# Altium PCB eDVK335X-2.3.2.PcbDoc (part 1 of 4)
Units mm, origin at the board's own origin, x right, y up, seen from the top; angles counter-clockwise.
Board outline 100.04 x 80.07 mm, 4 copper layers (Top Layer, Layer 1, Layer 2, Bottom Layer), stack 0.569 mm thick; 245 components, 272 nets, 1313 pads, 662 vias.
Unrouted connection lines stored in the file: 1.
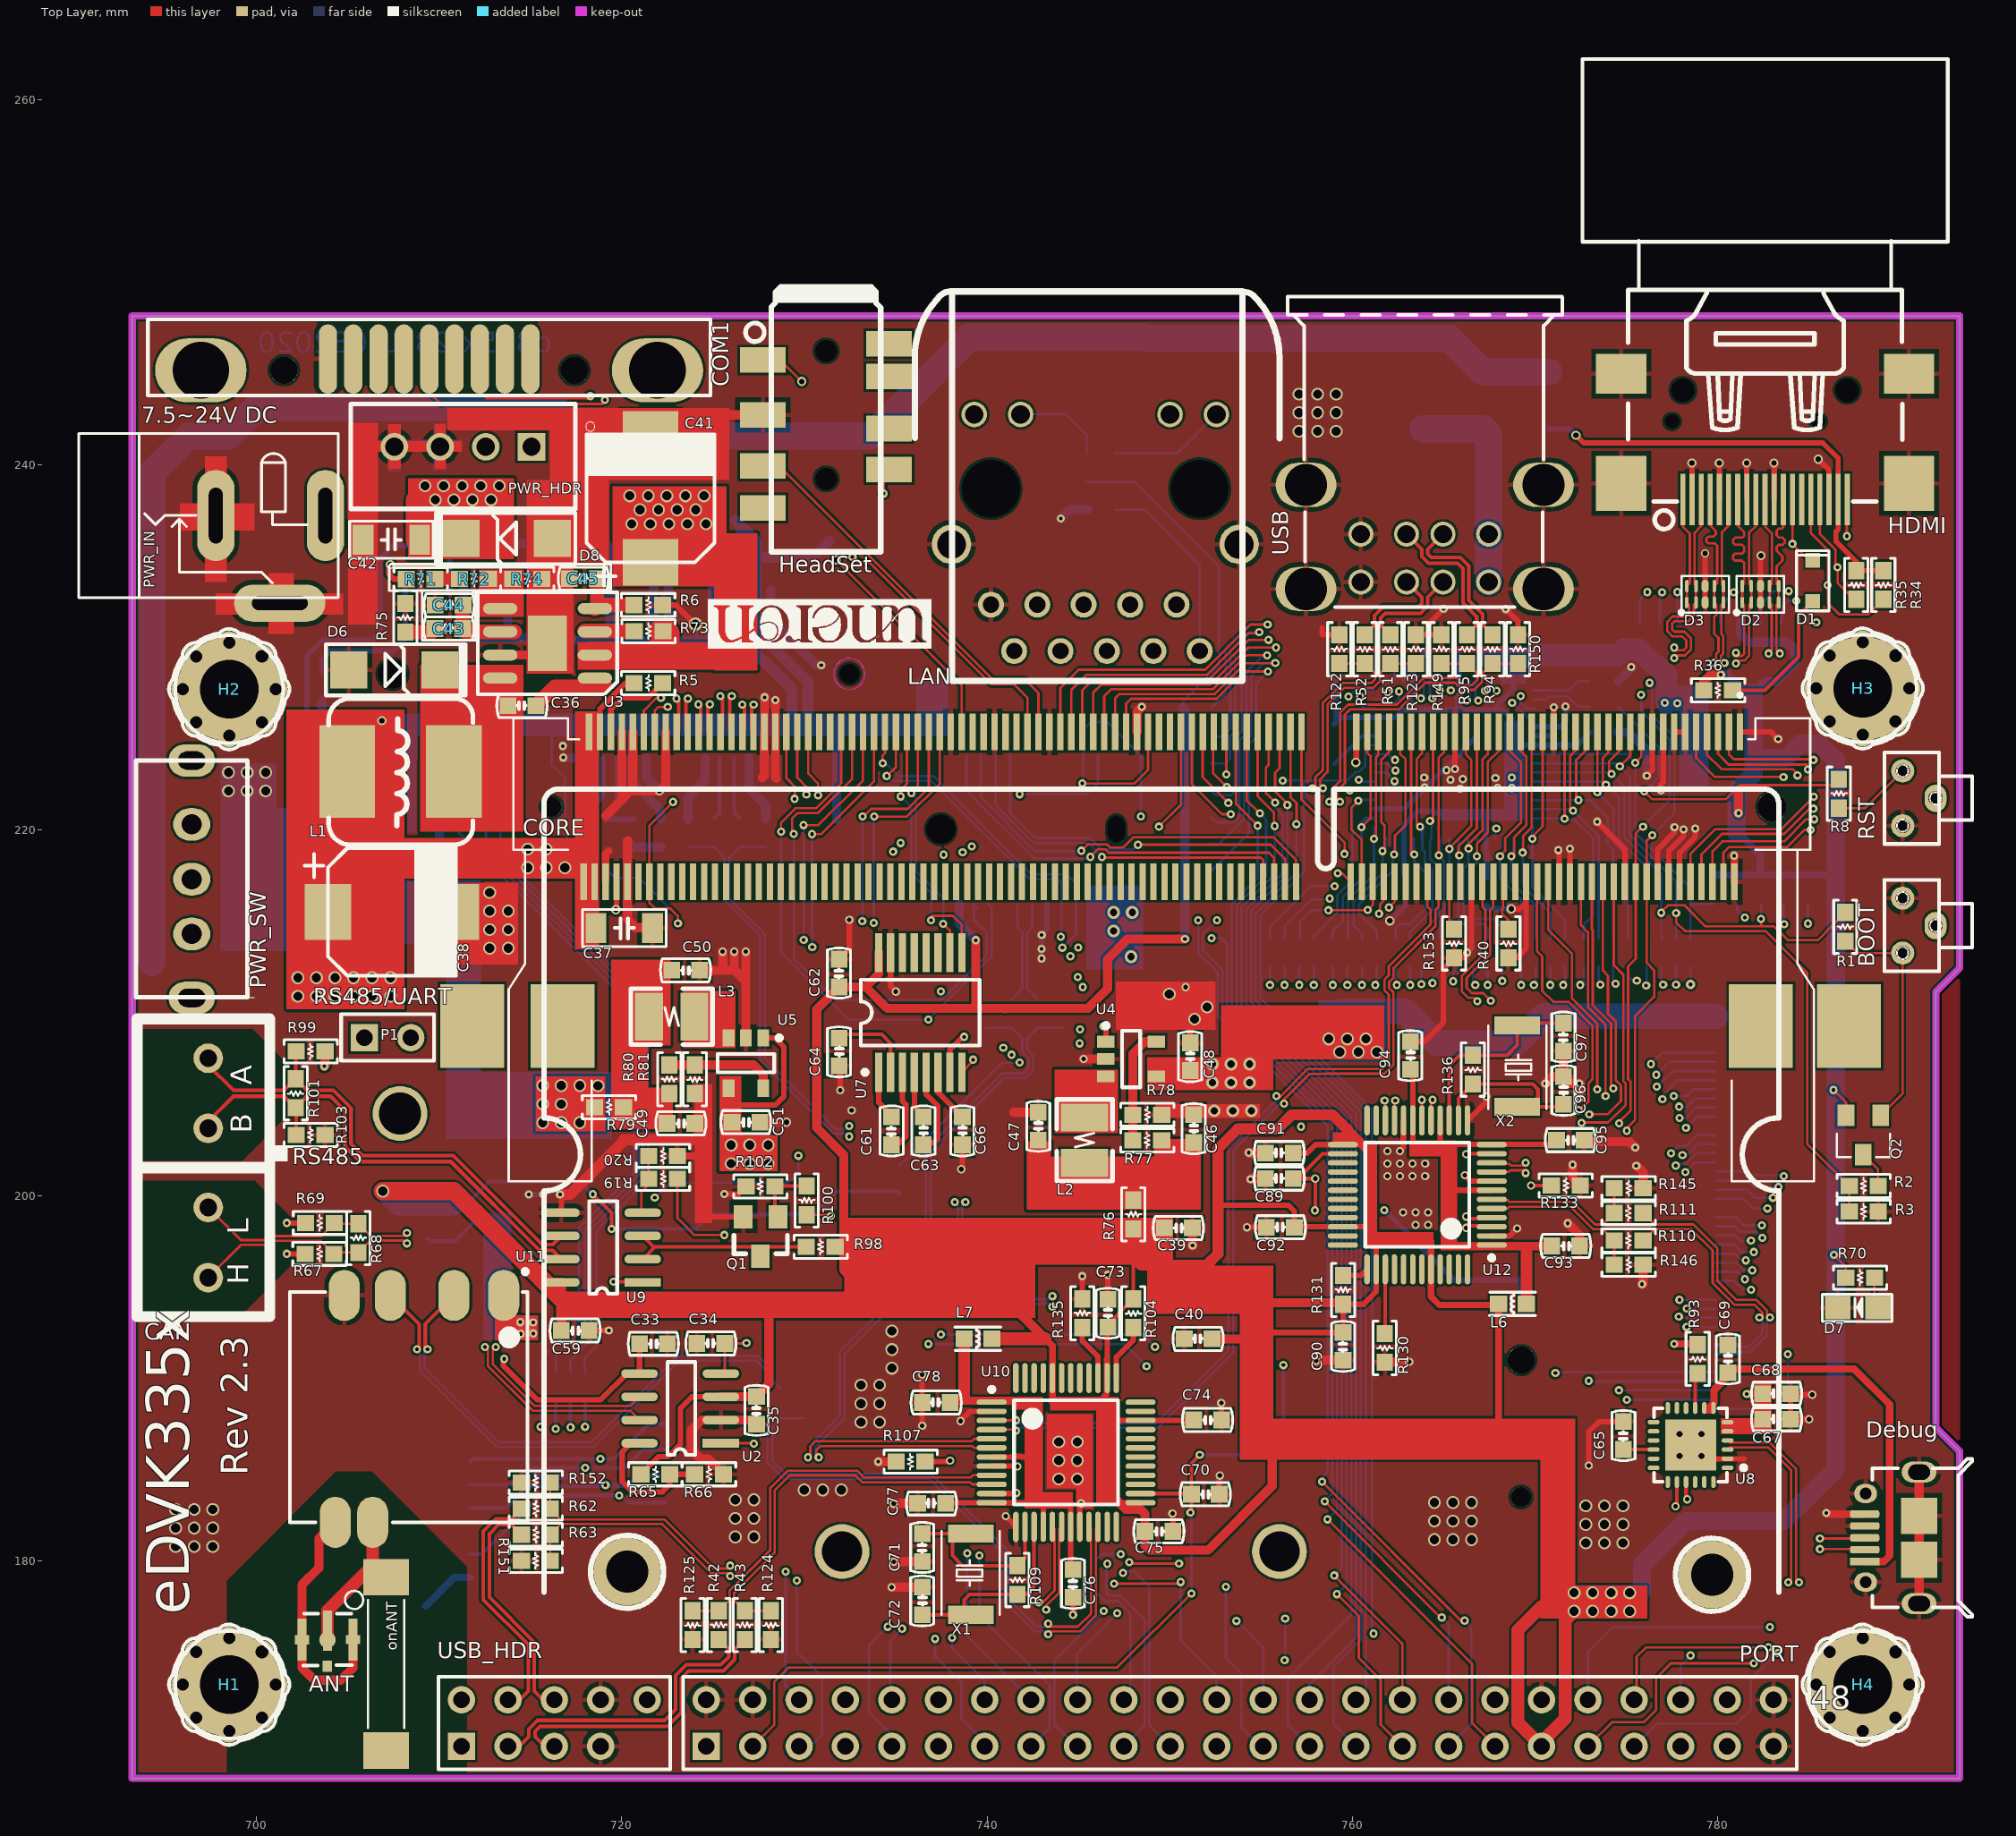
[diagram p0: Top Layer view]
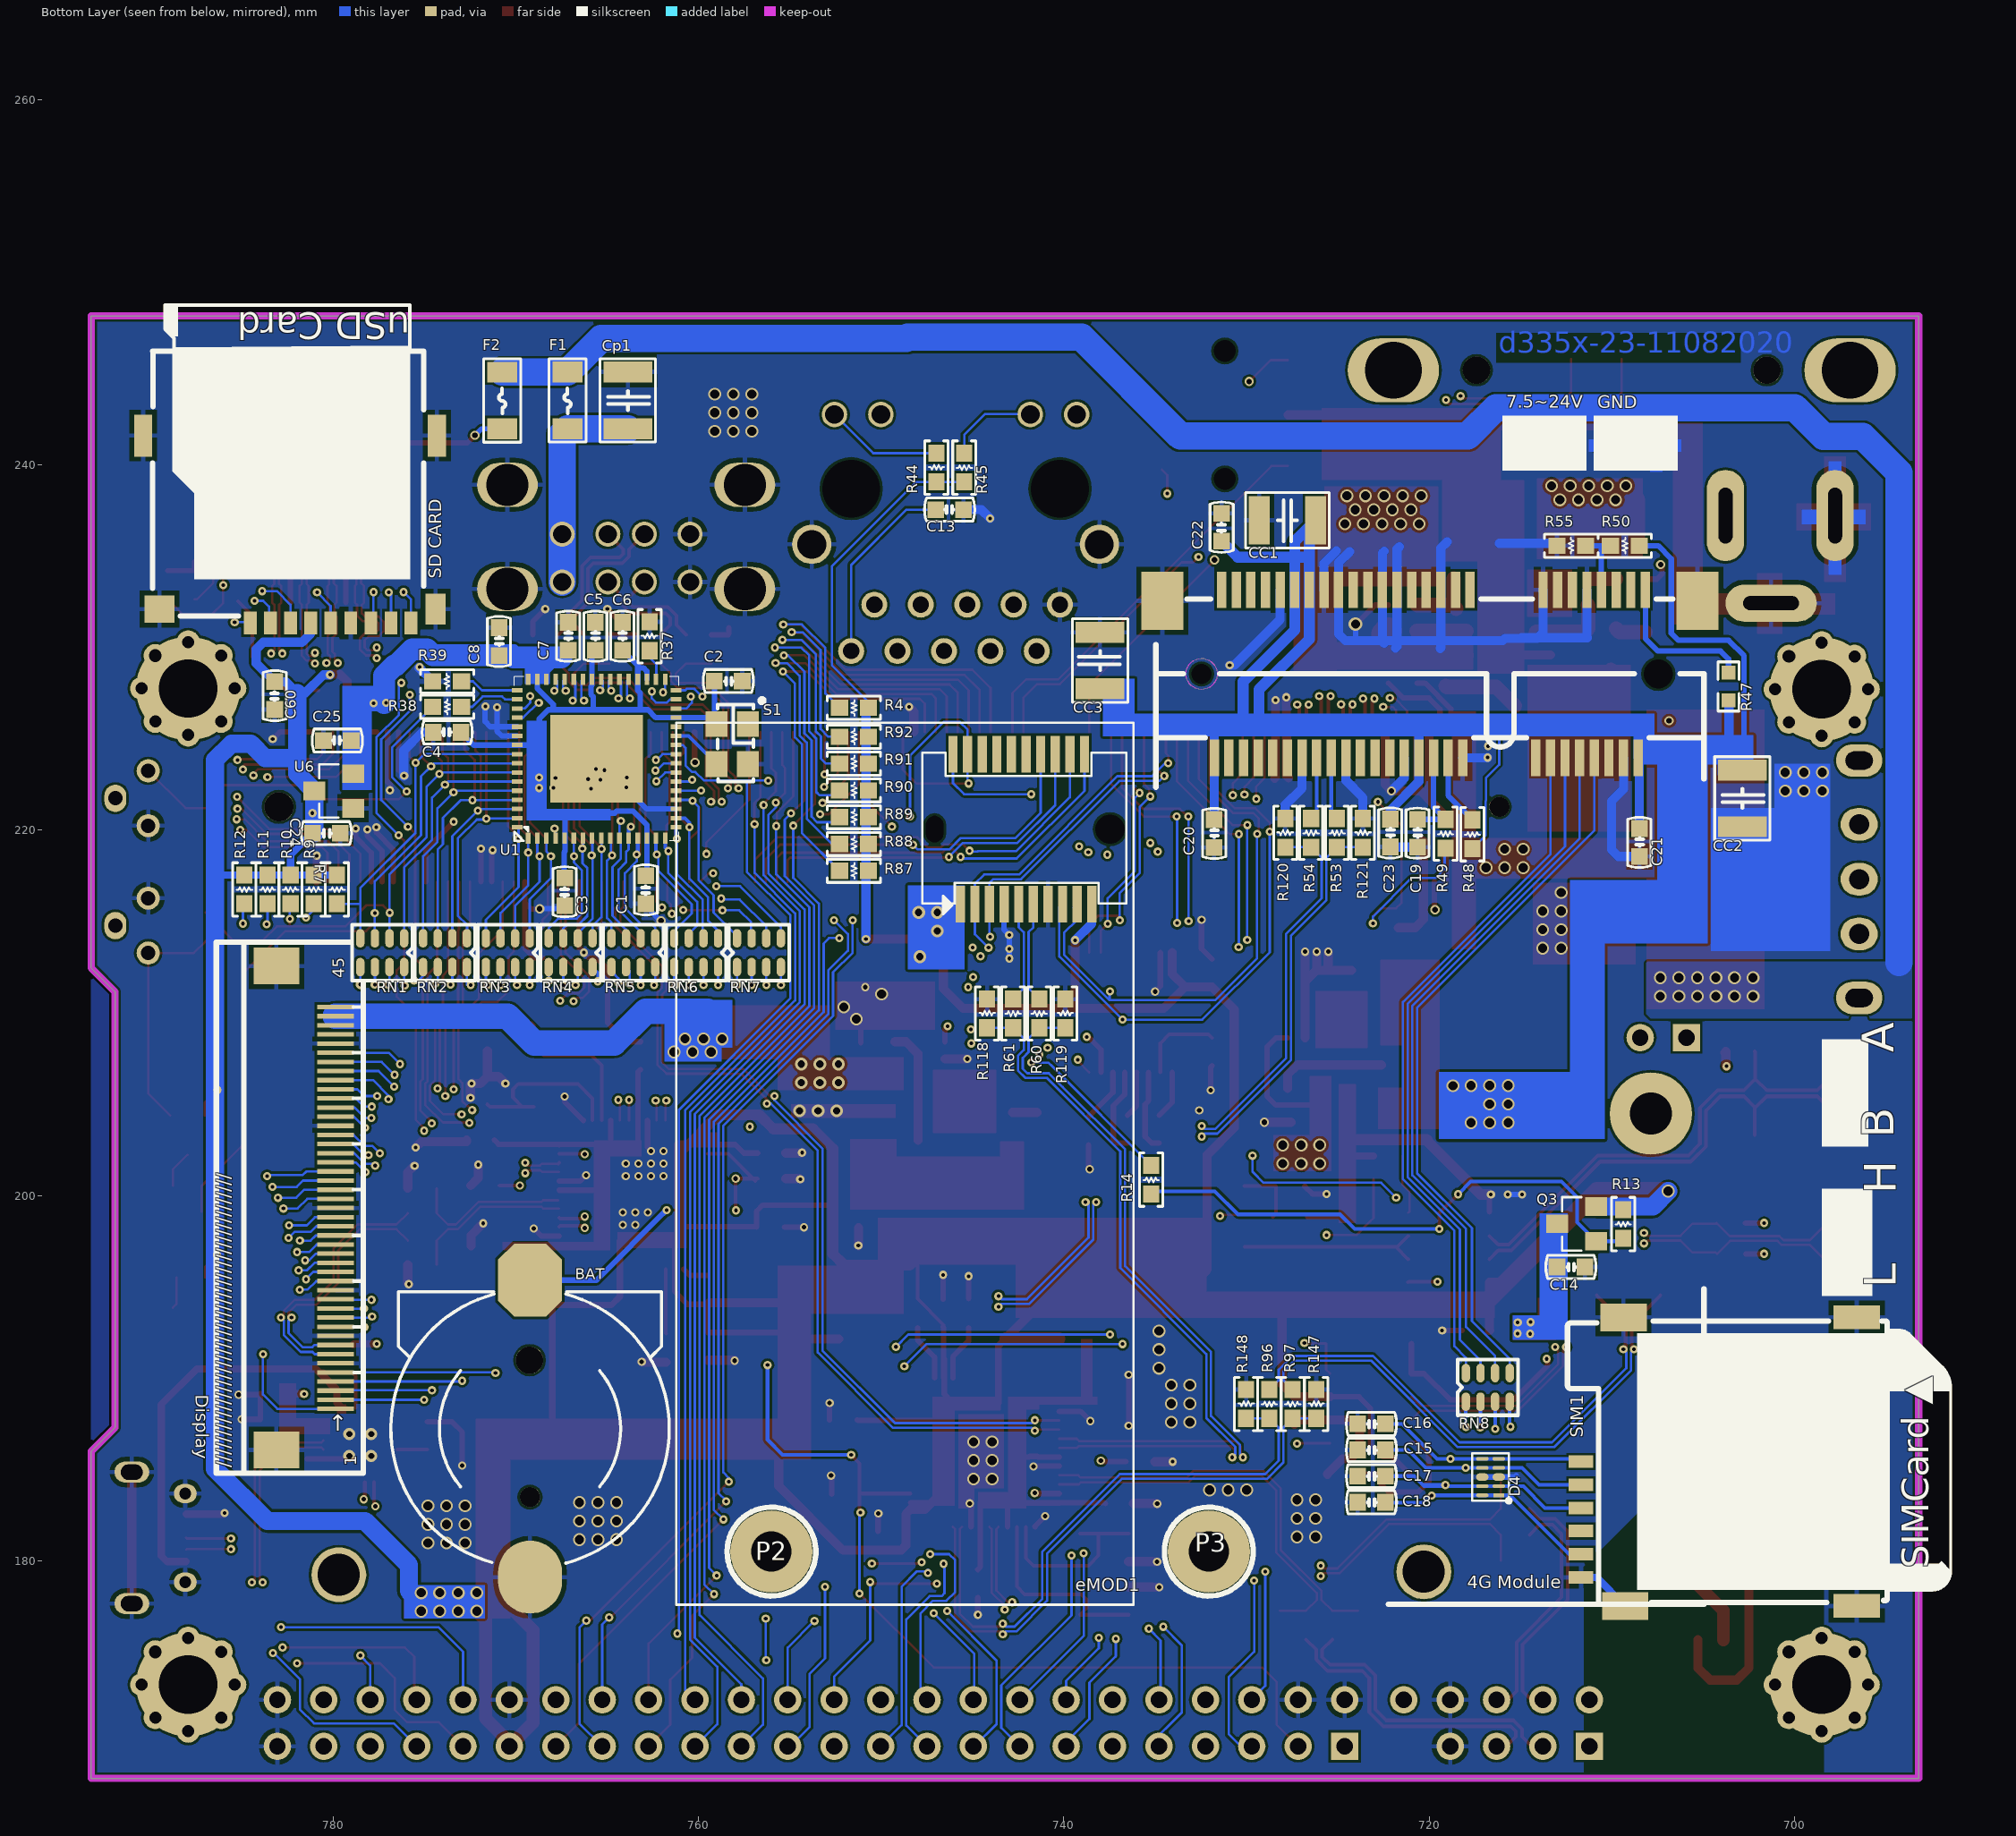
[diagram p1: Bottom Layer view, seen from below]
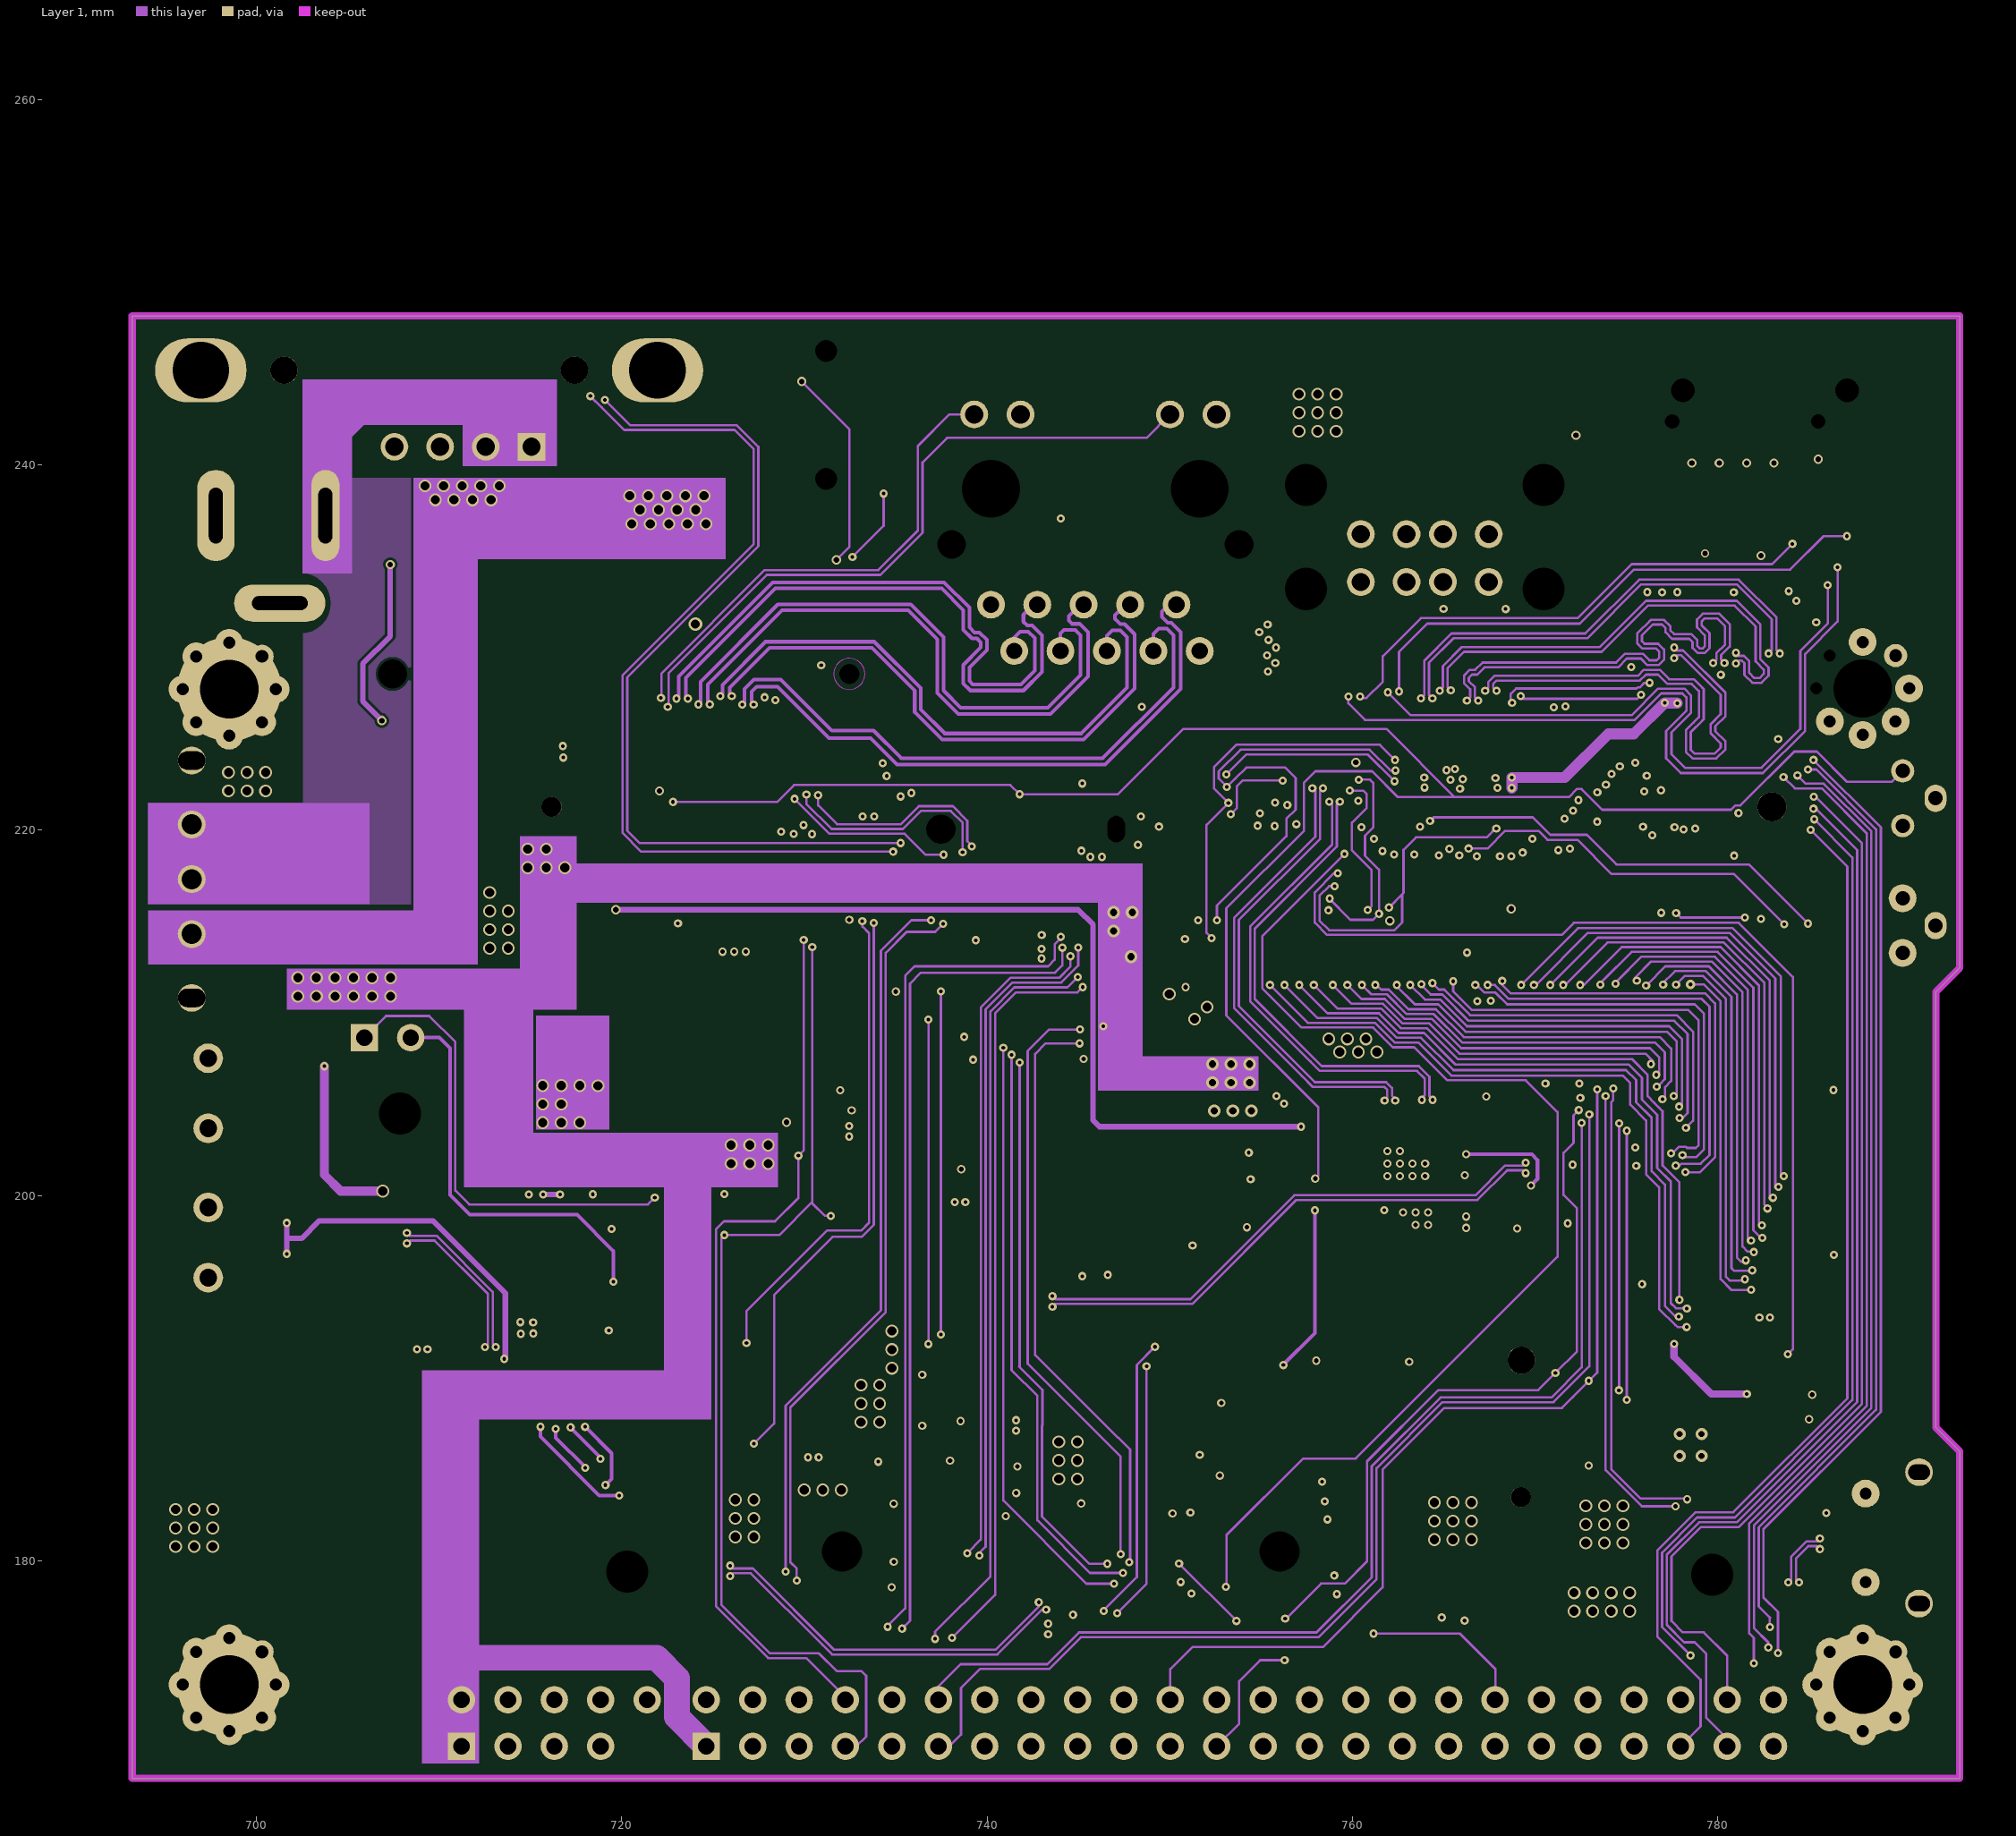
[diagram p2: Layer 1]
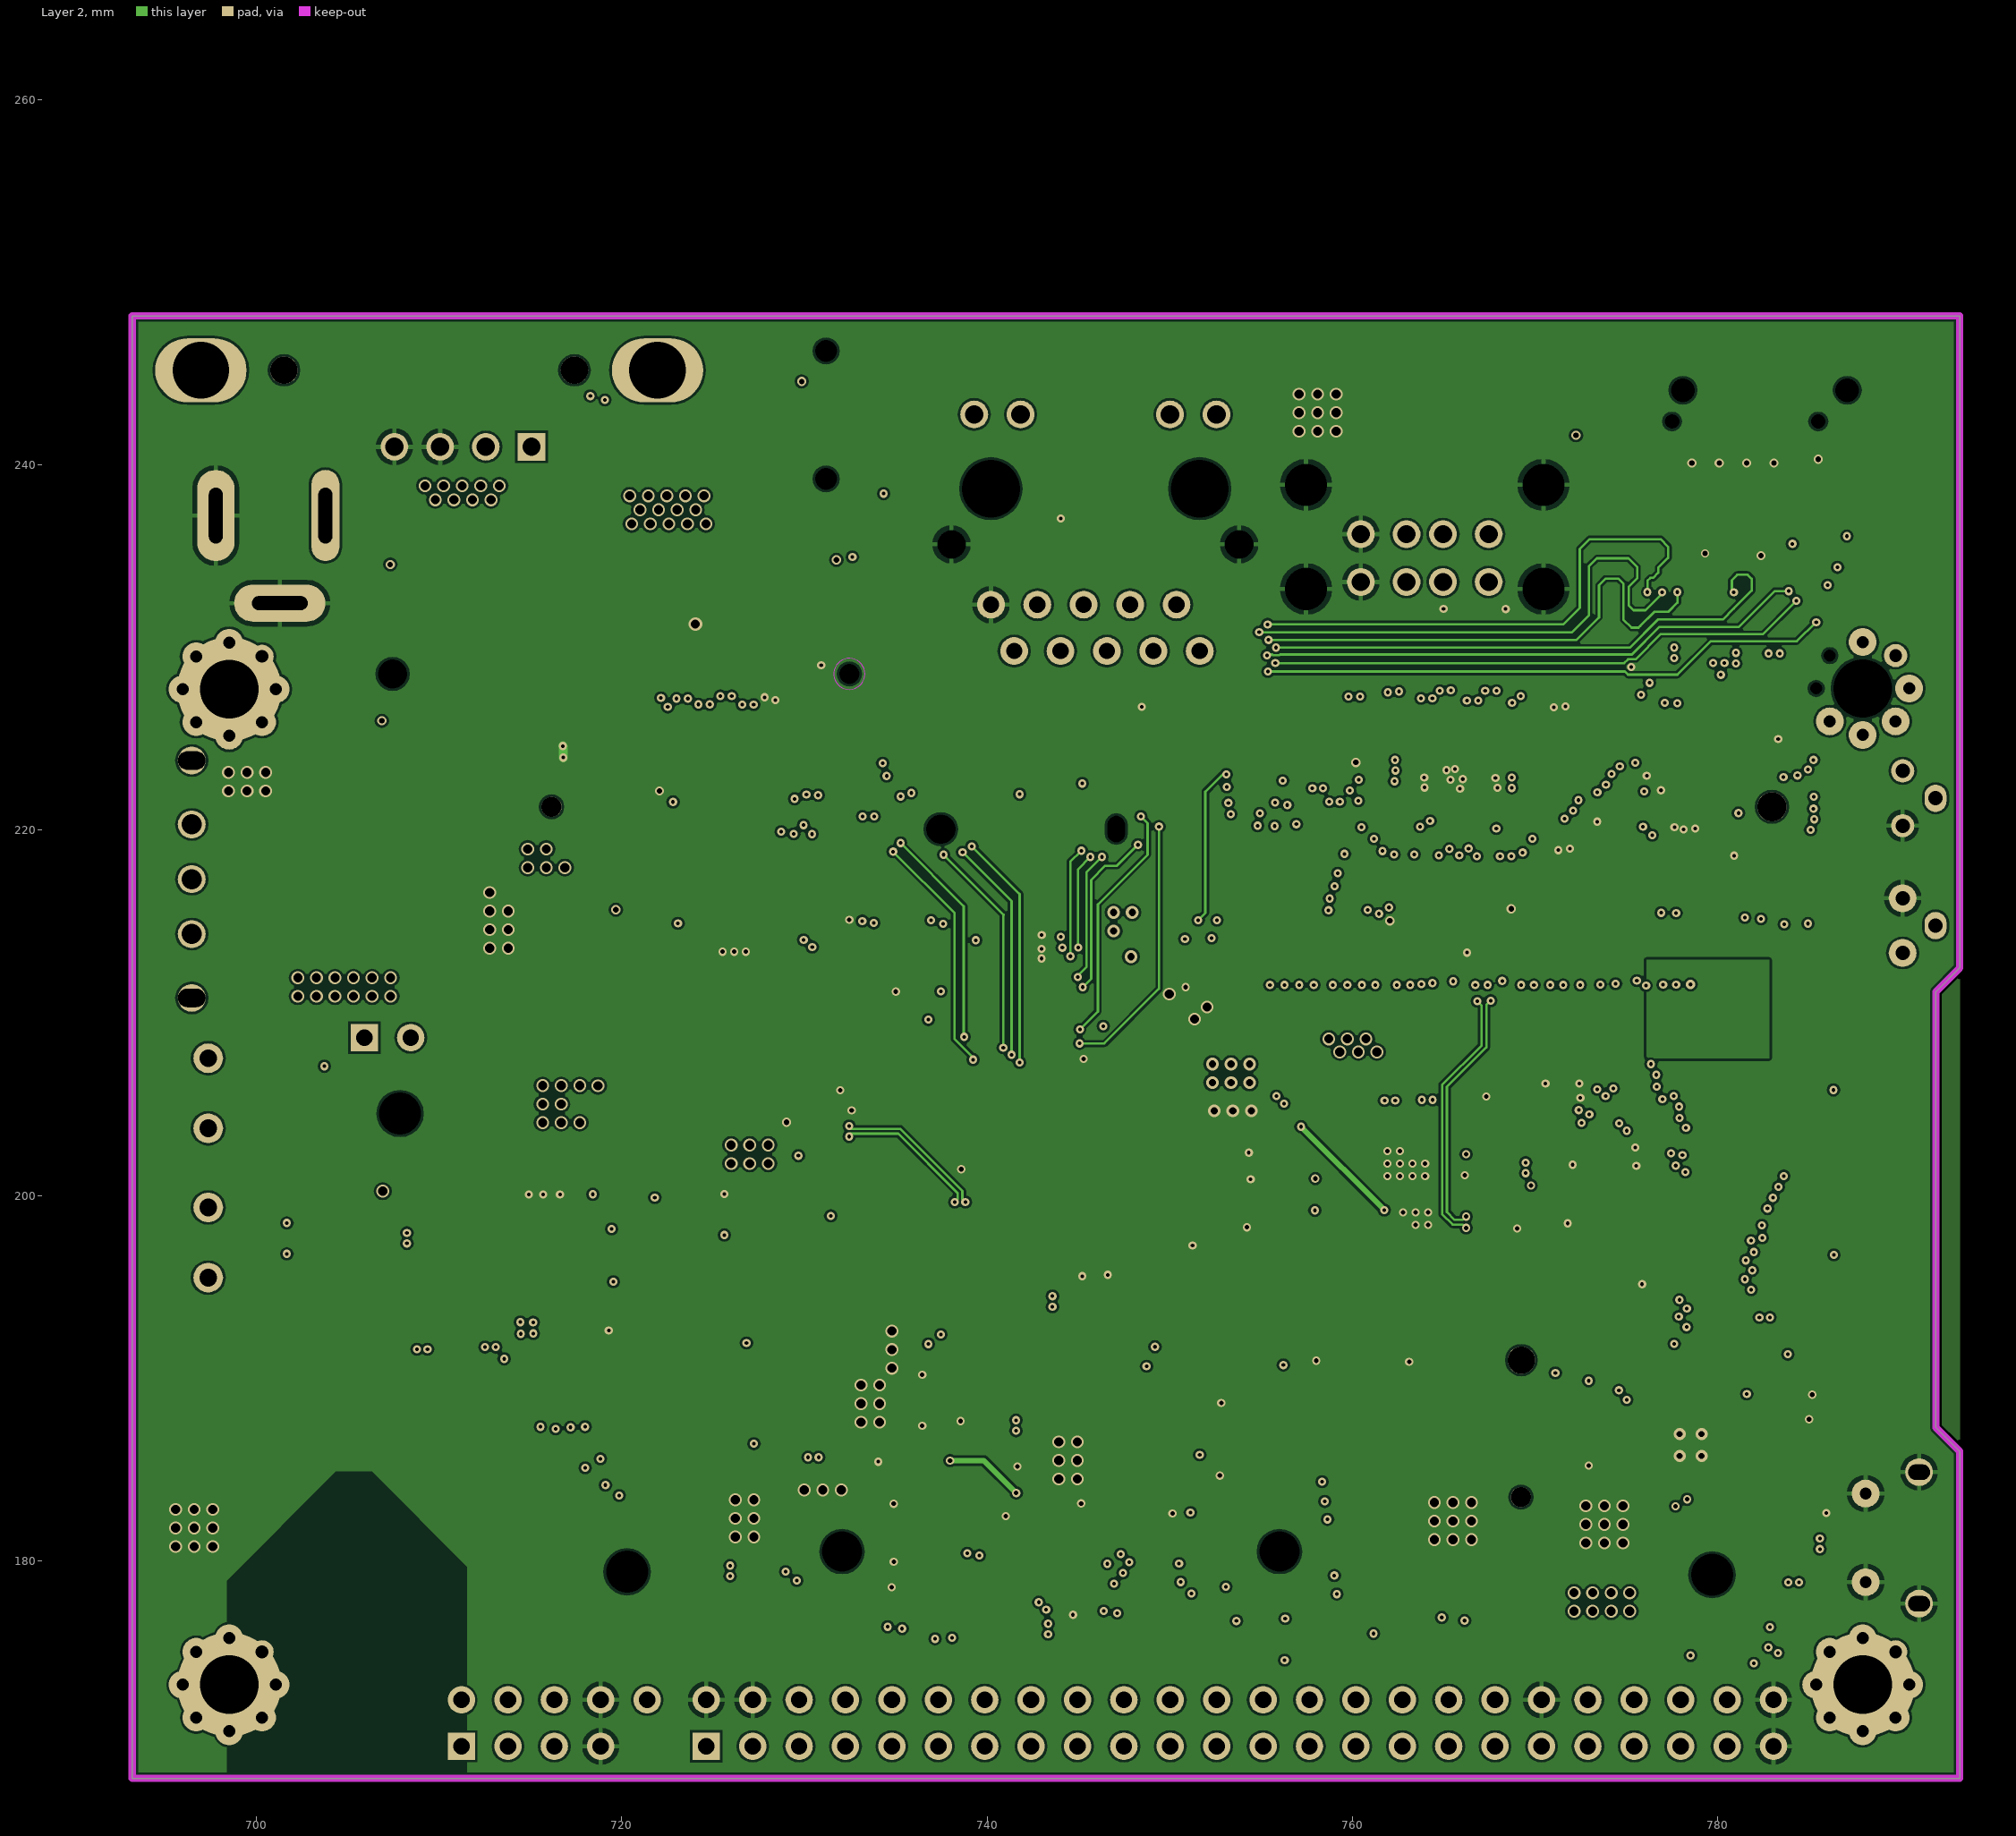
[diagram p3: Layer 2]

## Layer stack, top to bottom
Top Solder: solder mask 0.0102, Solder Resist, Dk 3.5
Top Layer: signal copper 0.0356
Dielectric 2: prepreg 0.0711, PP-006, Dk 4.1
Layer 1: signal copper 0.0178
Dielectric 1: dielectric 0.32, FR-4, Dk 4.8
Layer 2: signal copper 0.0178
Dielectric 3: prepreg 0.0711, PP-006, Dk 4.1
Bottom Layer: signal copper 0.0356
Bottom Solder: solder mask 0.0102, Solder Resist, Dk 3.5

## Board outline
693.2,168.09 693.2,248.158 793.242,248.158 793.242,212.462 791.94,211.16 791.94,187.3 793.242,185.998 793.242,168.09

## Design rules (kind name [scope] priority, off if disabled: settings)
Clearance [All] p1: gap=0.13 ignorepadtopadclearanceinfootprint=FALSE
DiffPairsRouting [All] p1: maxlimit=0.254 minlimit=0.13 mostfreqgap=0.13 toplayer_minwidth=0.13 toplayer_maxwidth=0.381 toplayer_prefwidth=0.2 midlayer1_minwidth=0.13 midlayer1_maxwidth=0.381 midlayer1_prefwidth=0.2 midlayer2_minwidth=0.13 midlayer2_maxwidth=0.381 midlayer2_prefwidth=0.2 bottomlayer_minwidth=0.13 bottomlayer_maxwidth=0.381 bottomlayer_prefwidth=0.2 maxuncoupledlength=12.7
HoleSize [All] p1: absolutevalues=TRUE maxlimit=5 minlimit=0.025 maxpercent=80.000 minpercent=20.000
PolygonConnect [All vs IsVia] p1: connectstyle=Direct reliefconductorwidth=0.254 reliefentries=4 polygonreliefangle="90 Angle" airgapwidth=0.254
PolygonConnect PolygonConnect_1 [All] p2: connectstyle=Relief reliefconductorwidth=0.254 reliefentries=4 polygonreliefangle="90 Angle" airgapwidth=0.254
RoutingVias [All] p1: holewidth=0.25 width=0.45 viastyle="Through Hole" minholewidth=0.2 minwidth=0.45 maxholewidth=3.5 maxwidth=5
SolderMaskExpansion [All] p1: expansion=0.102 istentingtop=FALSE
Width [All] p1: maxlimit=3 minlimit=0.13 preferedwidth=0.13
28 further rules are at their usual default settings.

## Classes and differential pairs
component class Others: H1 H2 H3 H4 PORT R8 RST
component class SODIMM-2: CORE R5
net class MMC0_D[3..0]: MMC0_D0 MMC0_D1 MMC0_D2 MMC0_D3
net class LCD_DATA[23..0]: LCD_DATA0 LCD_DATA1 LCD_DATA2 LCD_DATA3 LCD_DATA4 LCD_DATA5 LCD_DATA6 LCD_DATA7 LCD_DATA8 LCD_DATA9 LCD_DATA10 LCD_DATA11 LCD_DATA12 LCD_DATA13 LCD_DATA14 LCD_DATA15 LCD_DATA16 LCD_DATA17 LCD_DATA18 LCD_DATA19 LCD_DATA20 LCD_DATA21 LCD_DATA22 LCD_DATA23
net class AIN[7..0]: AIN0 AIN1 AIN2 AIN3 AIN4 AIN5 AIN6 AIN7
component class USBHUB2: C70 C71 C72 C73 C74 C75 C76 C77 C78 C89 C90 C91 C92 C93 C94 C95 C96 C97 Cp1 F1 L6 L7 R40 R42 R43 R51 R52 R53 R54 R60 R61 R62 R63 R94 R95 R96 R97 R104 R107 R109 R110 R111 R118 R119 R120 R121 R122 R123 R124 R125 R130 R131 R133 R135 R136 R145 R146 R147 R148 R149 R150 R151 R152 R153 U10 U12 USB USB_HDR X1 X2
component class UARTS: C61 C62 C63 C64 C65 C66 C67 C68 C69 COM1 Debug P1 Q1 R19 R20 R93 R98 R99 R100 R101 R102 R103 RS485 U7 U8 U9
component class Sound: HeadSet
component class SDCard: C59 C60 R4 R87 R88 R89 R90 R91 R92 "SD CARD"
component class Power: BAT C24 C25 C36 C37 C38 C39 C40 C41 C42 C43 C44 C45 C46 C47 C48 C49 C50 C51 D6 D7 D8 L1 L2 L3 PWR_HDR PWR_IN PWR_SW R6 R70 R71 R72 R73 R74 R75 R76 R77 R78 R79 R80 R81 U3 U4 U5 U6
component class CAN: C33 C34 C35 CAN R65 R66 R67 R68 R69 U2
component class mPCIUSB: "4G Module" C15 C16 C17 C18 C19 C20 C21 C22 C23 CC1 CC2 CC3 D4 P3 R47 R48 R49 R50 R55 RN8 SIM1
component class eMod-Wifi: ANT C14 eMOD1 onANT P2 Q3 R13 R14 U11
component class Eth: C13 LAN R44 R45
component class Display: C1 C2 C3 C4 C5 C6 C7 C8 D1 D2 D3 Display F2 HDMI R34 R35 R36 R37 R38 R39 RN1 RN2 RN3 RN4 RN5 RN6 RN7 S1 U1
component class Config: BOOT Q2 R1 R2 R3 R7 R9 R10 R11 R12
differential pair HUSB4: +HUSB4_P -HUSB4_N
differential pair HUSB7: +HUSB7_P -HUSB7_N
differential pair HUSB5: +HUSB5_P -HUSB5_N
differential pair HUSB6: +HUSB6_P -HUSB6_N
differential pair USB0_D: +USB0_D_P -USB0_D_N
differential pair USB1_D: +USB1_D_P -USB1_D_N
differential pair HUSB1: +HUSB1_P -HUSB1_N
differential pair HUSB2: +HUSB2_P -HUSB2_N
differential pair HUSB3: +HUSB3_P -HUSB3_N
differential pair HUSB0: +HUSB0_P -HUSB0_N
differential pair HDMI_TXC: +HDMI_TXC_P -HDMI_TXC_N
differential pair HDMI_TX2: +HDMI_TX2_P -HDMI_TX2_N
differential pair HDMI_TX1: +HDMI_TX1_P -HDMI_TX1_N
differential pair HDMI_TX0: +HDMI_TX0_P -HDMI_TX0_N
differential pair ETH1_MDI3: +ETH1_MDI3_P -ETH1_MDI3_N
differential pair ETH1_MDI2: +ETH1_MDI2_P -ETH1_MDI2_N
differential pair ETH1_MDI1: +ETH1_MDI1_P -ETH1_MDI1_N
differential pair ETH1_MDI0: +ETH1_MDI0_P -ETH1_MDI0_N
differential pair DIN1: +DIN1_P -DIN1_N
differential pair CAN: +CAN_P -CAN_N
differential pair AB: +AB_P -AB_N
differential pair 2D4: +2D4_P -2D4_N
differential pair 2D3: +2D3_P -2D3_N
differential pair 2D2: +2D2_P -2D2_N
differential pair 2D1: +2D1_P -2D1_N
differential pair 1D4: +1D4_P -1D4_N
differential pair 1D3: +1D3_P -1D3_N
differential pair 1D2: +1D2_P -1D2_N
differential pair 1D1: +1D1_P -1D1_N

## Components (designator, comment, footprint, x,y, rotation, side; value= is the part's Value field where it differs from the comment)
"4G Module" "miniPCIe 6.7H" MINI_PCIEX1-52P-2h-2 719.96,202.385 r0 bottom locked
ANT "20279-001E" IPXANT 703.89,175.732 r270 top
BAT "BAT Holder (CR1220)" BAT600 769.22,195.368 r0 bottom locked
BOOT "Push Button Right" KEY-A06#1 791.539,214.78 r90 top
C1 "2.2uF" C0603#1 762.88,216.74 r270 bottom
C2 "100nF" C0603#1 758.368,228.168 r180 bottom
C3 "2.2uF" C0603#1 767.32,216.63 r270 bottom
C4 "100nF" C0603#1 773.76,225.358 r0 bottom
C5 "2.2uF" C0603#1 765.646,230.62 r90 bottom
C6 "100nF" C0603#1 764.162,230.62 r90 bottom
C7 "100nF" C0603#1 767.13,230.62 r90 bottom
C8 "2.2uF" C0603#1 770.92,230.33 r90 bottom
C13 "220nF" C0603#1 746.25,237.55 r0 bottom
C14 "100nF" C0603#2 712.24,196.09 r180 bottom
C15 "33pF" C0603#1 723.16,186.071 r180 bottom
C16 "33pF" C0603#1 723.16,187.501 r180 bottom
C17 "33pF" C0603#1 723.16,184.64 r180 bottom
C18 "1uF" C0603#1 723.16,183.21 r180 bottom
C19 "100nF" C0603#1 720.636,219.839 r90 bottom
C20 "100nF" C0603#1 731.77,219.82 r90 bottom
C21 "100nF" C0603#1 708.49,219.33 r90 bottom
C22 "100nF" C0603#1 731.36,236.59 r270 bottom
C23 "100nF" C0603#1 722.13,219.85 r90 bottom
C24 "1uF" C0603#2 780.37,219.84 r180 bottom
C25 "1uF" C0603#2 779.77,224.91 r0 bottom
C33 "10nF" C0603#1 721.73,191.89 r0 top
C34 "10nF" C0603#1 724.88,191.9 r180 top
C35 "100nF" C0603#1 727.38,188.24 r270 top
C36 "100nF/50V" C0603#1 714.54,226.81 r180 top
C37 "22uF" C1206 720.14,214.65 r0 top
C38 "220uF/10V" CAPSOP 707.39,215.53 r0 top
C39 "10uF" C0603#2 750.47,198.23 r0 top
C40 "10uF" C0603#2 751.555,192.153 r180 top
C41 "100uF/50V" capsop 721.57,238.14 r90 top
C42 "10uF/50V" C1206 707.39,235.9 r180 top
C43 "4.7nF" C0603#1 710.53,231.04 r180 top
C44 "39pF" C0603#1 710.55,232.32 r180 top
C45 "10nF" C0603#1 717.9,233.77 r180 top
C46 "10uF" C0603#2 751.31,203.665 r90 top
C47 "100nF" C0603#1 742.801,203.792 r90 top
C48 "10uF" C0603#1 751.119,207.602 r90 top
C49 "10uF" C0603#1 723.24,203.952 r0 top
C50 "100nF" C0603#1 723.494,212.334 r0 top
C51 "10uF" C0603#1 726.796,204.016 r0 top
C59 "10uF" C0603#1 717.448,192.61 r0 top
C60 "100nF" C0603#1 783.2,227.37 r270 bottom
C61 "100nF" C0603#1 734.77,203.541 r270 top
C62 "100nF" C0603#1 731.895,212.183 r270 top
C63 "100nF" C0603#1 736.51,203.54 r90 top
C64 "100nF" C0603#1 731.895,207.865 r90 top
C65 "4.7uF" C0603#2 774.836,186.864 r270 top
C66 "100nF" C0603#1 738.65,203.54 r90 top
C67 "100nF" C0603#1 783.218,187.753 r180 top
C68 "4.7uF" C0603#2 783.218,189.15 r180 top
C69 "1uF" C0603#1 780.551,191.055 r90 top
C70 "1uF" C0603#1 751.946,183.651 r0 top
C71 "22pF" C0603#1 736.452,180.73 r270 top
C72 "22pF" C0603#1 736.452,177.809 r90 top
C73 "100nF" C0603#1 746.612,193.557 r90 top
C74 "100nF" C0603#1 752.073,187.715 r0 top
C75 "10uF" C0603#1 749.406,181.619 r0 top
C76 "100nF" C0603#1 744.707,178.761 r270 top
C77 "100nF" C0603#1 736.96,183.143 r180 top
C78 "10uF" C0603#1 737.214,188.667 r180 top
C89 "1uF" C0603#1 755.995,200.929 r180 top
C90 "100nF" C0603#1 759.488,191.744 r270 top
C91 "100nF" C0603#1 755.995,202.326 r180 top
C92 "10uF" C0603#1 756.059,198.262 r180 top
C93 "100nF" C0603#1 771.68,197.246 r0 top
C94 "100nF" C0603#1 763.171,207.66 r90 top
C95 "10uF" C0603#1 771.932,203.034 r0 top
C96 "22pF" C0603#1 771.553,205.755 r90 top
C97 "22pF" C0603#1 771.553,208.676 r270 top
CAN "KF350-3.5-2P" Terminal_X2 697.3,197.57 r180 top
CC1 "220uF" C1210 727.76,236.97 r180 bottom
CC2 "220uF" C1210 702.85,221.74 r90 bottom
CC3 "220uF" C1210 738.02,229.29 r270 bottom
COM1 "Ultra Thin DB9 SMD Male Right" DB9-UltraThin 709.46,245.83 r0 top
CORE "SODIMM-204" DDR3-335x 749.561,221.28 r270 top locked
Cp1 "100uF" C1210 763.863,243.532 r90 bottom value=100pF
D1 "RB751V40,115" SOD323 785.2,233.66 r90 top
D2 "AZ1045-04F" DFN2510P10E 782.335,232.918 r0 top
D3 "AZ1045-04F" DFN2510P10E 779.31,232.918 r0 top
D4 "AZ1045-04F" DFN2510P10E 716.64,184.59 r90 bottom
D6 "SSA33L/SS34" DO-214AC-SMA-12 707.56,228.78 r180 top
D7 "LED Red 0805" LED 787.668,193.859 r180 top
D8 "SMAJ12A" do-214ac-sma-12 713.71,235.97 r0 top
Debug "MicroUSB" micro_USB-B_hrs_ZX62D-B-5PA8 790.999,181.26 r90 top
Display "FPC - 45" con-fpc-p05-45p 782.86,199.945 r270 bottom locked
eMOD1 "Molex 74441-0001" 744410001 746.737,204.325 r180 bottom locked
F1 "Fuse 1A" F1206 767.165,243.532 r90 bottom
F2 "Fuse 1A" F1206 770.74,243.53 r90 bottom
H1 "Socket" HOLE320-4H#1 698.509,173.22 r0 top
H2 "Socket" HOLE320-4H#1 698.509,227.719 r0 top
H3 "Socket" HOLE320-4H#2 787.933,227.761 r0 top
H4 "Socket" HOLE320-4H#1 787.933,173.22 r0 top
HDMI "SMD HDMI" HDMI0119-20-RM-A-SMD 782.59,248.689 r180 top
HeadSet "PJ-393 SMD" PJ-393 731.11,242.95 r270 top
L1 "SWPA6045S6R8MT/6.8uH/3.5A" L7x7 707.89,223.21 r180 top
L2 "SLM25204R7MIT/4.7uH/1A" L1210 745.341,203.03 r270 top
L3 "SLM25204R7MIT/4.7uH/1A" L1210 722.732,209.794 r180 top
L6 "10uH" L0603 768.759,194.071 r0 top
L7 "10uH 200mA" L0603 739.5,192.16 r180 top value=10uH
LAN "JKM-0001NL" LPJG0820GENL 746.027,238.814 r180 top
onANT "AN9520" SMD_ANT9520 707.1,174.36 r270 top
P1 "Header 2" HDR1X2 705.91,208.65 r0 top
P2 "PCB Pillar (M2/3.5/3+1.2)" "PCB Pillar" 756.004,180.51 r180 bottom
P3 "PCB Pillar (M2/3.5/4+1.2)" "PCB Pillar" 732.06,180.51 r180 bottom
PORT "Header 24X2" HDR2X24 724.63,169.85 r0 top
PWR_HDR "XH 2.54 4Pin" JST_XHP-4 711.31,240.99 r0 top
PWR_IN "DC Plug (5.5*2.1) DC-005" DC-0005 697.38,237.23 r90 top
PWR_SW "Power Switch (SS12F44)" SW35 696.587,217.32 r270 top
Q1 "2N7002" S9013SMD 728.555,198.839 r180 top
Q2 "NC (SI2301BDS-T1-E3)" SOT-23#1 787.97,203.31 r180 top
Q3 "SI2301BDS-T1-E3" SOT-23#2 711.93,198.45 r90 bottom
R1 "1K" R0603#1 786.98,214.71 r90 top
R2 "10K" R0603#1 787.99,200.53 r180 top
R3 "NC" R0603#1 787.99,199.12 r180 top
R4 "10K" R0603#1 751.49,226.7 r180 bottom
R5 "0R" R0603#1 721.45,228.06 r0 top
R6 "NC (49.9K)" R0603#1 721.45,232.33 r0 top
R7 "47K" R0603#1 779.79,216.76 r270 bottom
R8 "10K" R0603#1 786.63,222 r90 top
R9 "47K" R0603#1 781.06,216.76 r270 bottom
R10 "47K" R0603#1 782.33,216.76 r270 bottom
R11 "47K" R0603#1 783.59,216.76 r270 bottom
R12 "47K" R0603#1 784.86,216.76 r270 bottom
R13 "10K" R0603#1 709.38,198.44 r270 bottom
R14 "NC" R0603#1 735.22,200.87 r270 bottom
R19 "NC" R0603#1 722.26,200.91 r0 top
R20 "0R" R0603#1 722.26,202.17 r0 top
R34 "1.5K, 1%" R0603#1 789.064,233.43 r270 top
R35 "1.5K, 1%" R0603#1 787.58,233.43 r270 top
R36 "27K, 1%" R0603#1 780.02,227.66 r180 top
R37 "10k, 1%" R0603#1 762.678,230.62 r90 bottom
R38 "10k, 1%" R0603#1 773.76,226.755 r180 bottom
R39 "0R" R0603#1 773.76,228.152 r0 bottom
R40 "0R" R0603#1 768.54,213.8 r270 top
R42 "22R" R0603#1 725.309,176.484 r90 top
R43 "22R" R0603#1 726.735,176.484 r90 top
R44 "470R" R0603#1 746.972,239.859 r90 bottom
R45 "470R" R0603#1 745.448,239.859 r270 bottom
R47 "10K" R0603#2 703.61,227.87 r270 bottom
R48 "10K/NC" R0603#1 717.63,219.78 r270 bottom
R49 "10K" R0603#1 719.1,219.81 r270 bottom
R50 "10K" R0603#1 709.29,235.58 r180 bottom
R51 "22R" R0603#1 762.075,229.915 r270 top
R52 "22R" R0603#1 760.678,229.915 r270 top
R53 "22R" R0603#1 725.046,219.86 r270 bottom
R54 "22R" R0603#1 726.462,219.86 r270 bottom
R55 "NC" R0603#1 712.22,235.58 r0 bottom
R60 "22R" R0603#1 741.347,209.97 r270 bottom
R61 "22R" R0603#1 742.773,209.97 r270 bottom
R62 "22R" R0603#1 715.293,182.856 r0 top
R63 "22R" R0603#1 715.293,181.43 r0 top
R65 "NC" R0603#1 721.84,184.74 r0 top
R66 "10K" R0603#1 724.78,184.74 r180 top
R67 "60R" R0603#1 703.453,196.81 r0 top
R68 "120R" R0603#1 705.58,197.67 r90 top
R69 "60R" R0603#1 703.48,198.5 r180 top
R70 "1K" R0603#1 787.795,195.51 r180 top
R71 "62K/1%" R0603#1 708.99,233.75 r0 top
R72 "1K/1%" R0603#1 711.91,233.76 r0 top
R73 "NC (365K)" R0603#1 721.47,230.9 r180 top
R74 "12K/1%" R0603#1 714.83,233.76 r0 top
R75 "49.9K" R0603#1 708.15,231.63 r90 top
R76 "0R" R0603#1 748.008,198.966 r90 top
R77 "200K 1%" R0603#1 748.77,203.03 r180 top
R78 "44.2K 1%" R0603#1 748.77,204.427 r0 top
R79 "0R" R0603#1 719.303,204.841 r0 top
R80 "200K 1%" R0603#1 722.605,206.365 r90 top
R81 "44.2K 1%" R0603#1 724.002,206.365 r270 top
R87 "10K" R0603#1 751.49,217.78 r180 bottom
R88 "10K" R0603#1 751.49,219.248 r180 bottom
R89 "10K" R0603#1 751.49,220.716 r180 bottom
R90 "10K" R0603#1 751.49,222.184 r180 bottom
R91 "10K" R0603#1 751.49,223.652 r180 bottom
R92 "10K" R0603#1 751.49,225.12 r180 bottom
R93 "10K" R0603#1 778.9,191.055 r270 top
R94 "22R" R0603#1 767.663,229.915 r270 top
R95 "22R" R0603#1 766.266,229.915 r270 top
R96 "22R" R0603#1 728.75,188.59 r270 bottom
R97 "22R" R0603#1 727.47,188.59 r270 bottom
R98 "10K" R0603#1 730.893,197.192 r180 top
R99 "1K" R0603#1 702.97,207.89 r180 top
R100 "100R" R0603#1 730.131,199.732 r90 top
R101 "120R" R0603#1 702.15,205.6 r270 top
R102 "47K" R0603#1 727.591,200.494 r180 top
R103 "1K" R0603#1 702.97,203.32 r180 top
R104 "100K" R0603#1 748.009,193.557 r270 top
R107 "680R" R0603#1 735.817,185.429 r180 top
R109 "1M" R0603#1 741.659,178.952 r90 top
R110 "22R" R0603#1 775.121,197.532 r180 top
R111 "22R" R0603#1 775.121,199.041 r180 top
R118 "15K" R0603#1 744.2,209.97 r90 bottom
R119 "15K" R0603#1 739.92,209.97 r90 bottom
R120 "15K" R0603#1 727.878,219.86 r90 bottom
R121 "15K" R0603#1 723.63,219.86 r90 bottom
R122 "15K" R0603#1 759.281,229.915 r90 top
R123 "15K" R0603#1 763.472,229.915 r90 top
R124 "15K" R0603#1 728.162,176.484 r270 top
R125 "15K" R0603#1 723.882,176.484 r270 top
R130 "100K" R0603#1 761.774,191.658 r270 top
R131 "100K" R0603#1 759.488,194.833 r90 top
R133 "680R" R0603#1 771.68,200.548 r0 top
R135 "100K" R0603#1 745.215,193.557 r90 top
R136 "1M" R0603#1 766.6,206.898 r270 top
R145 "15K" R0603#1 775.121,200.403 r0 top
R146 "15K" R0603#1 775.121,196.212 r0 top
R147 "15K" R0603#1 726.18,188.59 r90 bottom
R148 "15K" R0603#1 730.02,188.59 r90 bottom
R149 "15K" R0603#1 764.869,229.915 r90 top
R150 "15K" R0603#1 769.06,229.915 r90 top
R151 "15K" R0603#1 715.293,180.003 r180 top
R152 "15K" R0603#1 715.293,184.283 r180 top
R153 "0R" R0603#1 765.57,213.8 r270 top
RN1 "22R" rn-8p4r-0603 777.313,213.296 r0 bottom
RN2 "22R" rn-8p4r-0603 773.876,213.296 r0 bottom
RN3 "22R" rn-8p4r-0603 770.439,213.296 r0 bottom
RN4 "22R" rn-8p4r-0603 767.002,213.296 r0 bottom
RN5 "22R" rn-8p4r-0603 763.564,213.296 r0 bottom
RN6 "22R" rn-8p4r-0603 760.127,213.296 r0 bottom
RN7 "22R" rn-8p4r-0603 756.69,213.296 r180 bottom
RN8 "22R" rn-8p4r-0603 716.79,189.497 r180 bottom
RS485 "KF350-3.5-2P" Terminal_X2 697.3,205.74 r180 top
RST "Push Button Right" KEY-A06#2 791.539,221.75 r90 top
S1 "S3D12.000000B20F30T" OSCSC250P320X250X100-4N-2 757.301,225.822 r90 bottom
"SD CARD" "Micro SD Socket" uSD 782.4,238.84 r180 bottom locked
SIM1 "micro-sim 6Pin" micro-sim 703.68,185.43 r90 bottom locked
U1 "TDA19988" QFN64S9X9P5 765.575,223.914 r90 bottom locked
U2 "SN65HVD230D" max14840 723.268,188.093 r180 top
U3 "tps54332d" SOIC8-50X204-TH-2 715.94,230.23 r90 top
U4 "RT8059" SOT95P280X100-5N 747.881,207.475 r0 top
U5 "RT8059" SOT95P280X100-5N 726.796,207.254 r270 top
U6 "PMIC-XC6206P182MR(SOT23)" SOT-23#2 779.97,222.15 r90 bottom
U7 "MAX3232EEAE" SSOP16 736.34,210.024 r0 top
U8 "CP2104" QFN50P400X400X75-24N 778.512,186.344 r180 top
U9 "ISL83485" max14840 718.99,196.9 r180 top
U10 "GL852G" TSQFP50P900X900X160-48N 744.326,185.937 r0 top
U11 "RTL8188CTV/CUS" SOP200P1220X240-8N 708.34,188.26 r270 top
U12 "GL852G" TSQFP50P900X900X160-48N 763.552,200.04 r180 top
USB "USB2.0 TypeA Stacked (X2)" USB_DUAL_C080073-2 763.96,236.21 r180 top
USB_HDR "Header 5X2" HDR2X5 711.23,169.85 r0 top
X1 "12MHz 5032" CRYSTAL-5032-2p 736.502,179.46 r90 top
X2 "12MHz 5032" CRYSTAL-5032-2p 771.629,206.898 r270 top

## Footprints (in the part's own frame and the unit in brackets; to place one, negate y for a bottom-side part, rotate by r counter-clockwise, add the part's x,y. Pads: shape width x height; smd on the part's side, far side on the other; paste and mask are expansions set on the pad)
744410001 [mil] "MINI_PCIEX1-52P-2H-2"
  round 0 hole 37.4 slot 57.09 at 90 deg unplated: 0(-13.11,619.51)
  round 0 hole 62.99 unplated: 0(364.84,619.51)
  rect 20x79 smd: 1(42.01,458.09) 2(26.26,780.93) 3(73.5,458.09) 4(57.76,780.93) 5(105,458.09) 6(89.25,780.93) 7(136.5,458.09) 8(120.75,780.93) 9(167.99,458.09) 10(152.24,780.93) 11(199.49,458.09) 12(183.74,780.93) 13(230.98,458.09) 14(215.24,780.93) 15(262.48,458.09) 16(246.73,780.93) 17(293.98,458.09) 18(278.23,780.93) 19(325.47,458.09) 20(309.73,780.93)
  round 177.16 / inner round 60 / far side round 118.11 all layers, no hole: eMode_PIL(-364.84,-937.58)
  silkscreen extent -570,-1052 415,849, body extent -40,459 400,783, height 211
BAT600 [mm]
  round 1.1 hole 1.1 unplated: 0(0,11.878)
  round 1.5 hole 1.5 unplated: 0(0.025,4.378)
  oct 3.5x4 smd: 1(0,0)
  oval 3.5x4 smd: 2(0,16.256)
  silkscreen extent -7.62,0.63 7.62,15.49
C0603#1 [mil]
  rect 36x36 smd mask+2: 1(-30,0) 2(30,0)
  silkscreen extent -54,-25 54,25
C0603#2 [mil] "C0603"
  rect 36x36 smd: 1(-30,0) 2(30,0)
  silkscreen extent -54,-25 54,25
C1206 [mil]
  rect 45x65 smd mask+2: 1(-61,0) 2(61,0)
  silkscreen extent -90,-40 90,40
C1210 [mil] "C1206"
  rect 45x105 smd: 1(-61,0) 2(61,0)
  silkscreen extent -90,-59 90,60
CAPSOP [mil] "CAPSOP"
  rect 100x120 smd: 1(-136.8,-0.04) 2(138.79,-0.04)
  silkscreen extent -187,-139 139,138
capsop [mil] "CAPSOP"
  rect 100x120 smd: 1(-136.8,-0.04) 2(138.8,-0.04)
  silkscreen extent -187,-139 139,138
con-fpc-p05-45p [mm] "CON-FPC-P05-45P"
  rect 0.25x2 smd: 1(11.626,2.989) 2(11.126,2.989) 3(10.626,2.989) 4(10.126,2.989) 5(9.626,2.989) 6(9.126,2.989) 7(8.626,2.989) 8(8.126,2.989) 9(7.626,2.989) 10(7.126,2.989) 11(6.626,2.989) 12(6.126,2.989) 13(5.626,2.989) 14(5.126,2.989) 15(4.626,2.989) 16(4.126,2.989) 17(3.626,2.989) 18(3.126,2.989) 19(2.626,2.989) 20(2.126,2.989) 21(1.626,2.989) 22(1.126,2.989) 23(0.626,2.989) 24(0.126,2.989) 25(-0.374,2.989) 26(-0.874,2.989) 27(-1.374,2.989) 28(-1.874,2.989) 29(-2.374,2.989) 30(-2.874,2.989) 31(-3.374,2.989) 32(-3.874,2.989) 33(-4.374,2.989) 34(-4.874,2.989) 35(-5.374,2.989) 36(-5.874,2.989) 37(-6.374,2.989) 38(-6.874,2.989) 39(-7.374,2.989) 40(-7.874,2.989) 41(-8.374,2.989) 42(-8.874,2.989) 43(-9.374,2.989) 44(-9.874,2.989) 45(-10.374,2.989)
  rect 2x2.5 smd: A(13.875,-0.25) B(-12.625,-0.25)
  silkscreen extent -13.92,-3.54 15.15,4.51
CRYSTAL-5032-2p [mil] "CRYSTAL-5032-2P"
  rect 39x98.43 smd: 1(-95,-102.99) 2(80,-102.99)
  silkscreen extent -95,-165 85,-40
DB9-UltraThin [mm] "SOP, 18-Leads, Body 30.8x4.7mm (max), Pitch 1.38mm, IPC Medium Density"
  oval 1x3.8 smd: 1(5.54,-0.03) 2(2.77,-0.03) 3(0,-0.03) 4(-2.77,-0.03) 5(-5.545,-0.03) 6(4.15,-0.03) 7(1.385,-0.03) 8(-1.385,-0.03) 9(-4.155,-0.03)
  oval 5x3.5 hole 3.1: ""(-12.5,-0.65) ""(12.5,-0.65)
  round 1.5 hole 1.5: ""(-7.95,-0.65) ""(7.95,-0.65)
  silkscreen extent -15.4,-2.03 15.4,2.13, body extent -15.43,-2.05 15.41,1.83, height 12.55
DC-0005 [mil] "DC-0005"
  oval 197x80 / inner oval 196.85x60 / far side oval 197x80 hole 30 slot 120 at 0 deg: 1(0,-251.97)
  oval 197x80 hole 30 slot 120 at 0 deg: 2(0,-15.75)
  oval 80x197 hole 120 slot 30 at 0 deg: 3(-188.98,-153.54)
  silkscreen extent -177,-280 177,280, body extent -177,-280 177,280, height 150
DDR3-335x [mm]
  rect 2x0.35 smd: 1(-4.1,31.65) 2(4.1,31.35) 3(-4.1,31.05) 4(4.1,30.75) 5(-4.1,30.45) 6(4.1,30.15) 7(-4.1,29.85) 8(4.1,29.55) 9(-4.1,29.25) 10(4.1,28.95) 11(-4.1,28.65) 12(4.1,28.35) 13(-4.1,28.05) 14(4.1,27.75) 15(-4.1,27.45) 16(4.1,27.15) 17(-4.1,26.85) 18(4.1,26.55) 19(-4.1,26.25) 20(4.1,25.95) 21(-4.1,25.65) 22(4.1,25.35) 23(-4.1,25.05) 24(4.1,24.75) 25(-4.1,24.45) 26(4.1,24.15) 27(-4.1,23.85) 28(4.1,23.55) 29(-4.1,23.25) 30(4.1,22.95) 31(-4.1,22.65) 32(4.1,22.35) 33(-4.1,22.05) 34(4.1,21.75) 35(-4.1,21.45) 36(4.1,21.15) 37(-4.1,20.85) 38(4.1,20.55) 39(-4.1,20.25) 40(4.1,19.95) 41(-4.1,19.65) 42(4.1,19.35) 43(-4.1,19.05) 44(4.1,18.75) 45(-4.1,18.45) 46(4.1,18.15) 47(-4.1,17.85) 48(4.1,17.55) 49(-4.1,17.25) 50(4.1,16.95) 51(-4.1,16.65) 52(4.1,16.35) 53(-4.1,16.05) 54(4.1,15.75) 55(-4.1,15.45) 56(4.1,15.15) 57(-4.1,14.85) 58(4.1,14.55) 59(-4.1,14.25) 60(4.1,13.95) 61(-4.1,13.65) 62(4.1,13.35) 63(-4.1,13.05) 64(4.1,12.75) 65(-4.1,12.45) 66(4.1,12.15) 67(-4.1,11.85) 68(4.1,11.55) 69(-4.1,11.25) 70(4.1,10.95) 71(-4.1,10.65) 72(4.1,10.35) 73(-4.1,7.65) 74(4.1,7.35) 75(-4.1,7.05) 76(4.1,6.75) 77(-4.1,6.45) 78(4.1,6.15) 79(-4.1,5.85) 80(4.1,5.55) 81(-4.1,5.25) 82(4.1,4.95) 83(-4.1,4.65) 84(4.1,4.35) 85(-4.1,4.05) 86(4.1,3.75) 87(-4.1,3.45) 88(4.1,3.15) 89(-4.1,2.85) 90(4.1,2.55) 91(-4.1,2.25) 92(4.1,1.95) 93(-4.1,1.65) 94(4.1,1.35) 95(-4.1,1.05) 96(4.1,0.75) 97(-4.1,0.45) 98(4.1,0.15) 99(-4.1,-0.15) 100(4.1,-0.45) 101(-4.1,-0.75) 102(4.1,-1.05) 103(-4.1,-1.35) 104(4.1,-1.65) 105(-4.1,-1.95) 106(4.1,-2.25) 107(-4.1,-2.55) 108(4.1,-2.85) 109(-4.1,-3.15) 110(4.1,-3.45) 111(-4.1,-3.75) 112(4.1,-4.05) 113(-4.1,-4.35) 114(4.1,-4.65) 115(-4.1,-4.95) 116(4.1,-5.25) 117(-4.1,-5.55) 118(4.1,-5.85) 119(-4.1,-6.15) 120(4.1,-6.45) 121(-4.1,-6.75) 122(4.1,-7.05) 123(-4.1,-7.35) 124(4.1,-7.65) 125(-4.1,-7.95) 126(4.1,-8.25) 127(-4.1,-8.55) 128(4.1,-8.85) 129(-4.1,-9.15) 130(4.1,-9.45) 131(-4.1,-9.75) 132(4.1,-10.05) 133(-4.1,-10.35) 134(4.1,-10.65) 135(-4.1,-10.95) 136(4.1,-11.25) 137(-4.1,-11.55) 138(4.1,-11.85) 139(-4.1,-12.15) 140(4.1,-12.45) 141(-4.1,-12.75) 142(4.1,-13.05) 143(-4.1,-13.35) 144(4.1,-13.65) 145(-4.1,-13.95) 146(4.1,-14.25) 147(-4.1,-14.55) 148(4.1,-14.85) 149(-4.1,-15.15) 150(4.1,-15.45) 151(-4.1,-15.75) 152(4.1,-16.05) 153(-4.1,-16.35) 154(4.1,-16.65) 155(-4.1,-16.95) 156(4.1,-17.25) 157(-4.1,-17.55) 158(4.1,-17.85) 159(-4.1,-18.15) 160(4.1,-18.45) 161(-4.1,-18.75) 162(4.1,-19.05) 163(-4.1,-19.35) 164(4.1,-19.65) 165(-4.1,-19.95) 166(4.1,-20.25) 167(-4.1,-20.55) 168(4.1,-20.85) 169(-4.1,-21.15) 170(4.1,-21.45) 171(-4.1,-21.75) 172(4.1,-22.05) 173(-4.1,-22.35) 174(4.1,-22.65) 175(-4.1,-22.95) 176(4.1,-23.25) 177(-4.1,-23.55) 178(4.1,-23.85) 179(-4.1,-24.15) 180(4.1,-24.45) 181(-4.1,-24.75) 182(4.1,-25.05) 183(-4.1,-25.35) 184(4.1,-25.65) 185(-4.1,-25.95) 186(4.1,-26.25) 187(-4.1,-26.55) 188(4.1,-26.85) 189(-4.1,-27.15) 190(4.1,-27.45) 191(-4.1,-27.75) 192(4.1,-28.05) 193(-4.1,-28.35) 194(4.1,-28.65) 195(-4.1,-28.95) 196(4.1,-29.25) 197(-4.1,-29.55) 198(4.1,-29.85) 199(-4.1,-30.15) 200(4.1,-30.45) 201(-4.1,-30.75) 202(4.1,-31.05) 203(-4.1,-31.35) 204(4.1,-31.65)
  round 3.7 / inner round 0 / far side round 3 hole 2.3: 2(41.877,-29.27) 2(42.04,30.127)
  rect 4.6x3.5 smd: SH1(12,37.626) SH1(12,32.8) SH2(12,-32.8) SH2(12,-37.753)
  round 1.6 hole 1.6 unplated: ""(0,33.4)
  round 1.1 hole 1.1 unplated: ""(0,-33.4)
  silkscreen extent -6.22,-35.75 44.04,35.7
DFN2510P10E [mm] "DFN2510P10E"
  rect 0.2x0.6 smd: 1(-1,-0.45)
  oval 0.2x0.68 smd: 2(-0.5,-0.45) 4(0.5,-0.45) 5(1,-0.45) 6(1,0.45) 7(0.5,0.45) 9(-0.5,0.45) 10(-1,0.45)
  oval 0.4x0.68 smd: 3(0,-0.45) 8(0,0.45)
  silkscreen extent -1.43,-1.13 1.3,1
DO-214AC-SMA-12 [mil] "DO-214AC-SMA-12"
  rect 80x80 smd: 1(98.42,0) 2(-98.43,0)
  silkscreen extent -153,-55 148,55
do-214ac-sma-12 [mil] "DO-214AC-SMA-12"
  rect 80x80 smd: 1(98.43,0) 2(-98.42,0)
  silkscreen extent -153,-55 148,55
F1206 [mil] "F1206"
  rect 45x65 smd: 1(-61,0) 2(61,0)
  silkscreen extent -90,-40 90,40
HDMI0119-20-RM-A-SMD [mm] "HDMI0119-20-RM-A"
  rect 0.28x2.82 smd mask+0.08: 1(4.5,10.59) 2(4,10.59) 3(3.5,10.59) 4(3,10.59) 5(2.5,10.59) 6(2,10.59) 7(1.5,10.59) 8(1,10.59) 9(0.5,10.59) 10(0,10.59) 11(-0.5,10.59) 12(-1,10.59) 13(-1.5,10.59) 14(-2,10.59) 15(-2.5,10.59) 16(-3,10.59) 17(-3.5,10.59) 18(-4,10.59) 19(-4.5,10.59)
  rect 2.75x3 smd: 20(-7.875,9.699) 21(7.875,9.699)
  rect 2.75x2.2 smd: 22(-7.875,3.699) 23(7.875,3.699)
  round 0 hole 1.3 unplated: 24(4.5,4.599) 25(-4.5,4.599)
  silkscreen extent -10,-13.53 10,12.2
HDR1X2 [mm] "Connector; Header; 2 Position"
  rect 1.5x1.5 hole 0.9: 1(0,0)
  round 1.5 hole 0.9: 2(2.54,0)
  silkscreen extent -1.27,-1.27 3.81,1.27
HDR2X5 [mm] "Connector; Header; 5x2 Position"
  rect 1.5x1.5 hole 0.9: 1(0,0)
  round 1.5 hole 0.9: 2(0,2.54) 3(2.54,0) 4(2.54,2.54) 5(5.08,0) 6(5.08,2.54) 7(7.62,0) 8(7.62,2.54) 10(10.16,2.54)
  silkscreen extent -1.27,-1.27 11.43,3.81
HDR2X24 [mm] "Connector; Header; 24x2 Position"
  rect 1.5x1.5 hole 0.9: 1(0,0)
  round 1.5 hole 0.9: 2(0,2.54) 3(2.54,0) 4(2.54,2.54) 5(5.08,0) 6(5.08,2.54) 7(7.62,0) 8(7.62,2.54) 9(10.16,0) 10(10.16,2.54) 11(12.7,0) 12(12.7,2.54) 13(15.24,0) 14(15.24,2.54) 15(17.78,0) 16(17.78,2.54) 17(20.32,0) 18(20.32,2.54) 19(22.86,0) 20(22.86,2.54) 21(25.4,0) 22(25.4,2.54) 23(27.94,0) 24(27.94,2.54) 25(30.48,0) 26(30.48,2.54) 27(33.02,0) 28(33.02,2.54) 29(35.56,0) 30(35.56,2.54) 31(38.1,0) 32(38.1,2.54) 33(40.64,0) 34(40.64,2.54) 35(43.18,0) 36(43.18,2.54) 37(45.72,0) 38(45.72,2.54) 39(48.26,0) 40(48.26,2.54) 41(50.8,0) 42(50.8,2.54) 43(53.34,0) 44(53.34,2.54) 45(55.88,0) 46(55.88,2.54) 47(58.42,0) 48(58.42,2.54)
  silkscreen extent -1.27,-1.27 59.69,3.81
HOLE320-4H#1 [mm] "HOLE320-4H"
  round 1.27 / inner round 1.524 / far side round 1.27 hole 0.66: 0(-2.546,0) 0(-1.8,-1.8) 0(-1.8,1.8) 0(0,-2.546) 0(0,2.546) 0(1.8,-1.8) 0(2.546,0)
  round 5.7 hole 3.2: 0(0,0)
  round 1.27 hole 0.7: 0(1.8,1.8)
  silkscreen extent -3.3,-3.3 3.3,3.3
HOLE320-4H#2 [mm] "HOLE320-4H"
  round 1.27 / inner round 0 / far side round 1.27 hole 0.66: 0(-2.546,0) 0(-1.8,1.8)
  round 1.27 / inner round 1.524 / far side round 1.27 hole 0.66: 0(-1.8,-1.8) 0(0,-2.546) 0(0,2.546) 0(1.8,-1.8) 0(2.546,0)
  round 5.7 / inner round 0 / far side round 5.7 hole 3.2: 0(0,0)
  round 1.27 hole 0.7: 0(1.8,1.8)
  silkscreen extent -3.3,-3.3 3.3,3.3
IPXANT [mm]
  rect 2.2x0.5 smd: 1(-0.457,0)
  round 0.9 smd: 1(0.052,0)
  rect 0.6x0.5 smd: 1(1.499,-0.013)
  rect 0.5x0.8 smd: 2(0.038,1.397) 2(0.051,-1.397)
  rect 2.3x0.5 smd: 2(0.038,1.397) 2(0.051,-1.397)
  silkscreen extent -1.37,-1.32 1.46,1.34
JST_XHP-4 [mm]
  rect 1.508x1.508 hole 1: 1(3.75,0)
  round 1.508 hole 1: 2(1.25,0) 3(-1.25,0) 4(-3.75,0)
  silkscreen extent -6.15,-3.4 7.22,2.35
KEY-A06#1 [mil] "KEY-A06"
  round 50 / inner round 60 / far side round 50 hole 31: 1(59.05,55.87) 2(-59.06,55.87)
  oval 59.06x47.24 hole 31: 3(0,-15)
  silkscreen extent -100,-96 100,97
KEY-A06#2 [mil] "KEY-A06"
  round 50 hole 31: 1(59.05,55.87) 2(-59.06,55.87)
  oval 59.06x47.24 hole 31: 3(0,-15)
  silkscreen extent -100,-96 100,97
L7x7 [mil] "L7X7"
  rect 120x200 smd: 1(-115.2,-0.34) 2(115.2,-0.34)
  silkscreen extent -159,-157 157,160
L0603 [mil] "L0603"
  rect 37x35 smd: 1(-30,0) 2(30,0)
  silkscreen extent -49,-25 50,25
L1210 [mil]
  rect 60x102.36 smd mask+2: 1(-49,0) 2(49,0)
  silkscreen extent -88,-60 88,60
LED [mm] "LED"
  rect 1.4x1.27 smd: 1(-1.105,0) 2(1.105,0)
  silkscreen extent -1.86,-0.72 1.95,0.75
LPJG0820GENL [mil] "LPJG0820GENL"
  round 56 / inner round 60 / far side round 56 hole 35: 1(-221,354.5) 2(-171,254.5) 3(-121,354.5) 4(-71,254.5) 5(-21,354.5) 6(29,254.5) 7(79,354.5) 8(129,254.5) 9(179,354.5) 10(229,254.5)
  round 55 / inner round 60 / far side round 55 hole 40: 11(-257,-155.5) 12(-157,-155.5) 13(165,-155.5) 14(265,-155.5)
  round 0 hole 125 unplated: " "(-221,4.5) " "(229,4.5)
  round 85 / inner round 60 / far side round 85 hole 62: S1(-306,124.5) S2(314,124.5)
  silkscreen extent -393,-421 393,419
max14840 [mm]
  rect 2x0.47 smd: 1(-2.159,1.651)
  oval 2x0.47 smd: 2(-2.159,0.381) 3(-2.159,-0.889) 4(-2.159,-2.159) 5(2.295,-2.159) 6(2.295,-0.889) 7(2.295,0.381) 8(2.295,1.651)
  silkscreen extent -0.76,-2.79 0.76,2.29
micro-sim [mm]
  rect 0.686x1.346 smd: 1(-5.07,8.015) 2(-2.53,8.015) 3(0.01,8.015) 4(-6.34,8.015) 5(-3.8,8.015) 6(-1.26,8.015)
  rect 1.524x2.54 smd: G1(-7.9,5.59) G2(7.9,5.68)
  rect 1.3x2.54 smd: G3(-7.9,-7.09) G4(7.9,-7.09)
  silkscreen extent -7.7,-12.23 7.7,8.75
micro_USB-B_hrs_ZX62D-B-5PA8 [mil] "MICRO_USB-B_HRS_ZX62D-B-5PA8"
  rect 16x63 smd: 1(-51.18,116.29)
  rrect50% 16x63 smd: 2(-25.59,116.29) 3(0,116.29) 4(25.59,116.29) 5(51.18,116.29)
  oval 45x75 / inner round 60 / far side oval 45x75 hole 33 slot 47.24 at 90 deg: G1(-141.73,-0.84) G4(141.74,-0.84)
  rect 78x78 smd: G2(-47.24,-0.84) G3(47.25,-0.84)
  oval 41.34x49.21 / inner round 60 / far side oval 41.34x49.21 hole 25.59: G5(-95.47,114.37) G6(95.47,114.37)
  silkscreen extent -170,-115 170,100
MINI_PCIEX1-52P-2h-2 [mm] "MINI_PCIEX1-52P-2H-2"
  rect 0.508x2.007 smd: 1(-11.8,-30.775) 2(-11.4,-21.575) 3(-11,-30.775) 4(-10.6,-21.575) 5(-10.2,-30.775) 6(-9.8,-21.575) 7(-9.4,-30.775) 8(-9,-21.575) 9(-8.6,-30.775) 10(-8.2,-21.575) 11(-7.8,-30.775) 12(-7.4,-21.575) 13(-7,-30.775) 14(-6.6,-21.575) 15(-6.2,-30.775) 16(-5.8,-21.575) 17(-2.2,-30.775) 18(-1.8,-21.575) 19(-1.4,-30.775) 20(-1,-21.575) 21(-0.6,-30.775) 22(-0.2,-21.575) 23(0.2,-30.775) 24(0.6,-21.575) 25(1,-30.775) 26(1.4,-21.575) 27(1.8,-30.775) 28(2.2,-21.575) 29(2.6,-30.775) 30(3,-21.575) 31(3.4,-30.775) 32(3.8,-21.575) 33(4.2,-30.775) 34(4.6,-21.575) 35(5,-30.775) 36(5.4,-21.575) 37(5.8,-30.775) 38(6.2,-21.575) 39(6.6,-30.775) 40(7,-21.575) 41(7.4,-30.775) 42(7.8,-21.575) 43(8.2,-30.775) 44(8.6,-21.575) 45(9,-30.775) 46(9.4,-21.575) 47(9.8,-30.775) 48(10.2,-21.575) 49(10.6,-30.775) 50(11,-21.575) 51(11.4,-30.775) 52(11.8,-21.575)
  round 0 hole 1.6 unplated: G1(-12.5,-26.175)
  round 0 hole 1.092 unplated: G2(12.5,-26.175)
  rect 2.311x3.2 smd: M1(-14.65,-30.175) M2(14.65,-30.175)
  round 4.5 / inner round 1.524 / far side round 3 all layers, no hole: mPCIe_PIL(12.1,21.875)
  round 4.5 / inner round 1.524 / far side round 3 hole 2.3: ""(-12.095,-2.105)
  Multi-Layer keep-out circle w0.025: c12.5,-26.175 r0.851
  silkscreen extent -15,-30.27 15,24.77
OSCSC250P320X250X100-4N-2 [mm] "Crystal, SM; 4 Leads; Body 3.2 x 2.5 x 1.0 mm (LxWxH)"
  rect 1.4x1.2 smd: 1(0,0) 2(-2.2,0) 3(-2.2,1.7) 4(0,1.7)
  silkscreen extent -3.15,-0.9 1.39,1.65, body extent -2.85,-0.65 0.75,2.3, height 1.1
"PCB Pillar" [mm]
  round 4.5 / inner round 0 / far side round 3 hole 2.2: 2(0,0)
  silkscreen extent -2.43,-2.43 2.43,2.43
PJ-393 [mm] "Audio Jack"
  rect 1.4x2.5 smd mask+0.08: 1(-2.79,-3.38) 2(0.21,-3.38) 3(3.01,-3.38) 4(5.31,-3.38) 5(-3.69,3.52) 6(-1.89,3.52) 7(0.96,3.52) 8(3.21,3.52)
  round 0 hole 1.2 unplated: 24(3.71,0.07) 25(-3.29,0.07)
  silkscreen extent -6.79,-4.33 7.71,3.07
QFN50P400X400X75-24N [mm] "QFN, 24-Leads, Body 4.0x4.0mm (max), Pitch 0.50mm, IPC Medium Density"
  oval 0.65x0.25 smd: 1(-2.025,1.25) 2(-2.025,0.75) 3(-2.025,0.25) 4(-2.025,-0.25) 5(-2.025,-0.75) 6(-2.025,-1.25) 13(2.025,-1.25) 14(2.025,-0.75) 15(2.025,-0.25) 16(2.025,0.25) 17(2.025,0.75) 18(2.025,1.25)
  oval 0.25x0.65 smd: 7(-1.25,-2.025) 8(-0.75,-2.025) 9(-0.25,-2.025) 10(0.25,-2.025) 11(0.75,-2.025) 12(1.25,-2.025) 19(1.25,2.025) 20(0.75,2.025) 21(0.25,2.025) 22(-0.25,2.025) 23(-0.75,2.025) 24(-1.25,2.025)
  rect 2.8x2.8 smd: 25(0,0)
  silkscreen extent -3.03,-2 2,2, body extent -2,-2 2,2, height 0.75
QFN64S9X9P5 [mm] "QFN64S9X9P5"
  rect 0.6x0.25 smd mask+0.051: 1(-4.35,3.75) 2(-4.35,3.25) 3(-4.35,2.75) 4(-4.35,2.25) 5(-4.35,1.75) 6(-4.35,1.25) 7(-4.35,0.75) 8(-4.35,0.25) 9(-4.35,-0.25) 10(-4.35,-0.75) 11(-4.35,-1.25) 12(-4.35,-1.75) 13(-4.35,-2.25) 14(-4.35,-2.75) 15(-4.35,-3.25) 16(-4.35,-3.75) 33(4.35,-3.75) 34(4.35,-3.25) 35(4.35,-2.75) 36(4.35,-2.25) 37(4.35,-1.75) 38(4.35,-1.25) 39(4.35,-0.75) 40(4.35,-0.25) 41(4.35,0.25) 42(4.35,0.75) 43(4.35,1.25) 44(4.35,1.75) 45(4.35,2.25) 46(4.35,2.75) 47(4.35,3.25) 48(4.35,3.75)
  rect 0.25x0.6 smd mask+0.051: 17(-3.75,-4.35) 18(-3.25,-4.35) 19(-2.75,-4.35) 20(-2.25,-4.35) 21(-1.75,-4.35) 22(-1.25,-4.35) 23(-0.75,-4.35) 24(-0.25,-4.35) 25(0.25,-4.35) 26(0.75,-4.35) 27(1.25,-4.35) 28(1.75,-4.35) 29(2.25,-4.35) 30(2.75,-4.35) 31(3.25,-4.35) 32(3.75,-4.35) 49(3.75,4.35) 50(3.25,4.35) 51(2.75,4.35) 52(2.25,4.35) 53(1.75,4.35) 54(1.25,4.35) 55(0.75,4.35) 56(0.25,4.35) 57(-0.25,4.35) 58(-0.75,4.35) 59(-1.25,4.35) 60(-1.75,4.35) 61(-2.25,4.35) 62(-2.75,4.35) 63(-3.25,4.35) 64(-3.75,4.35)
  rect 4.8x5.05 smd mask+0.051: 65(0,0)
  silkscreen extent -4.5,-4.5 4.5,4.5
R0603#1 [mil] "R0603"
  rect 37x35 smd: 1(-31,0) 2(31,0)
  silkscreen extent -58,-25 58,25
R0603#2 [mil]
  rect 30x30 smd mask+2: 1(-30,0) 2(30,0)
  silkscreen extent -53,-23 53,23
rn-8p4r-0603 [mil] "RN-8P4R-0603"
  oval 18x40 smd: 1(-47.25,-31) 2(-15.75,-31) 3(15.75,-31) 4(47.25,-31) 5(47.25,31) 6(15.75,31) 7(-15.75,31) 8(-47.25,31)
  silkscreen extent -65,-60 65,60
S9013SMD [mil]
  rect 40x50 smd: B(-0.02,-0.16) C(37.98,84.84) E(74.98,-0.16)
  silkscreen extent -20,40 95,80
SMD_ANT9520 [mm]
  rect 2x2.5 smd: P$FEED(-4.75,0) P$GND(4.75,0)
  silkscreen extent -4,-2.25 3.5,1
SOD323 [mil] "SOD323"
  rect 31.5x31.5 smd mask+2: 1(44.29,0) 2(-44.29,0)
  silkscreen extent -65,-35 65,35
SOIC8-50X204-TH-2 [mil] "SOIC8-50X204-TH-2"
  oval 24x74 smd: 1(-75,-102) 2(-25,-102) 3(25,-102) 4(75,-102) 5(75,102) 6(25,102) 7(-25,102) 8(-75,102)
  rect 120x84 smd: 9(0,0)
  silkscreen extent -110,-150 110,150
SOP200P1220X240-8N [mm] "SOP, 8-Leads, Body 13.0x12.4mm (max), Pitch 2.00mm, IPC Medium Density"
  oval 2.8x1.7 smd: 1(-6.275,5.2) 2(-6.275,2.475) 3(-6.275,-1) 4(-6.275,-3.525) 5(6.15,-4.025) 6(6.15,-1.975)
  silkscreen extent -7.7,-6.5 6.15,6.5, body extent -6.2,-6.5 6.2,6.5, height 2.4
SOT95P280X100-5N [mm]
  rect 0.95x0.65 smd mask+0.051: 1(-1.375,0.95) 2(-1.375,0) 3(-1.375,-0.95) 4(1.375,-0.95) 5(1.375,0.95)
  silkscreen extent -1.5,-1.55 0.5,1.95, body extent -0.9,-1.55 0.9,1.55, height 1
SOT-23#1 [mil]
  rect 36x46 smd: 1(-37.5,-42.5) 2(37.5,-42.5) 3(0,42.5)
  silkscreen extent -58,-3 58,48
SOT-23#2 [mil]
  rect 40x47.24 smd: 1(-37.4,-41.73) 2(37.4,-41.73) 3(0,41.73)
  silkscreen extent -58,-10 58,31
SSOP16 [mm] "SSOP; 16 Leads; Body Width 5.3 mm; Pitch 0.65 mm"
  rect 0.4x2.15 smd: 1(-2.275,-3.275) 2(-1.625,-3.275) 3(-0.975,-3.275) 4(-0.325,-3.275) 5(0.325,-3.275) 6(0.975,-3.275) 7(1.625,-3.275) 8(2.275,-3.275) 9(2.275,3.275) 10(1.625,3.275) 11(0.975,3.275) 12(0.325,3.275) 13(-0.325,3.275) 14(-0.975,3.275) 15(-1.625,3.275) 16(-2.275,3.275)
  silkscreen extent -3.25,-3.4 3.25,1.8
SW35 [mil] "SW35"
  oval 70x100 / inner round 60 / far side oval 70x100 hole 39.37 slot 59.06 at 90 deg: 1(-255.91,-5) 5(255.91,-5)
  oval 70x80 / inner round 60 / far side oval 70x80 hole 43.31: 2(-118.11,-5) 3(0,-5) 4(118.11,-5)
  silkscreen extent -256,-125 255,130, body extent -293,-130 293,130, height 150
Terminal_X2 [mm]
  round 1.624 hole 0.97: 1(-0.063,-1.778) 2(-0.063,2.062)
  silkscreen extent -3.43,-3.94 3.83,4.19
TSQFP50P900X900X160-48N [mm] "TSQFP, 48-Leads, Body 9.0x9.0mm (max), Pitch 0.50mm, IPC Medium Density"
  oval 1.65x0.3 smd: 1(-4.075,2.75) 2(-4.075,2.25) 3(-4.075,1.75) 4(-4.075,1.25) 5(-4.075,0.75) 6(-4.075,0.25) 7(-4.075,-0.25) 8(-4.075,-0.75) 9(-4.075,-1.25) 10(-4.075,-1.75) 11(-4.075,-2.25) 12(-4.075,-2.75) 25(4.075,-2.75) 26(4.075,-2.25) 27(4.075,-1.75) 28(4.075,-1.25) 29(4.075,-0.75) 30(4.075,-0.25) 31(4.075,0.25) 32(4.075,0.75) 33(4.075,1.25) 34(4.075,1.75) 35(4.075,2.25) 36(4.075,2.75)
  oval 0.3x1.65 smd: 13(-2.75,-4.075) 14(-2.25,-4.075) 15(-1.75,-4.075) 16(-1.25,-4.075) 17(-0.75,-4.075) 18(-0.25,-4.075) 19(0.25,-4.075) 20(0.75,-4.075) 21(1.25,-4.075) 22(1.75,-4.075) 23(2.25,-4.075) 24(2.75,-4.075) 37(2.75,4.075) 38(2.25,4.075) 39(1.75,4.075) 40(1.25,4.075) 41(0.75,4.075) 42(0.25,4.075) 43(-0.25,4.075) 44(-0.75,4.075) 45(-1.25,4.075) 46(-1.75,4.075) 47(-2.25,4.075) 48(-2.75,4.075)
  silkscreen extent -4.2,-2.85 2.85,3.57, body extent -3.5,-3.5 3.5,3.5, height 1.6
USB_DUAL_C080073-2 [mil] "USB_DUAL_C080073-2"
  round 54 / inner round 60 / far side round 54 hole 39: D1(-137.79,0) D2(-39.37,0) D3(39.37,0) D4(137.8,0) U1(-137.79,103.15) U2(-39.37,103.15) U3(39.37,103.15) U4(137.8,103.15)
  oval 131x95 / inner round 60 / far side oval 131x95 hole 91: G1(-255.91,-106.3) G2(255.91,-106.3) G3(255.91,118.11) G4(-255.91,118.11)
  silkscreen extent -297,-512 295,157
uSD [mm]
  rect 0.7x1.25 smd: 1(-2.134,-7.493) 2(-1.034,-7.493) 3(0.066,-7.493) 4(1.166,-7.493) 5(2.266,-7.493) 6(3.366,-7.493) 7(4.466,-7.493) 8(5.566,-7.493) 9(6.666,-7.493)
  rect 1.65x1.5 smd: 10(-7.112,-6.731)
  rect 1.1x1.7 smd: 11(8.001,-6.731)
  rect 1x2.3 smd: 12(-8.001,2.767) 13(8.074,2.767)
  round 0 hole 0.8 unplated: ""(-3.1,3.538) ""(4.9,3.538)
  silkscreen extent -7.49,-7.11 7.37,9.9

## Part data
"4G Module": library part CON50A_2
ANT: library part SMA
BAT: library part BATTERY
BOOT RST: library part "SW PUSHBUTTON_0"
C1 C3 C5 C8: library part "CAP SMD", "CAP CER 2.2UF 6.3V 10% X5R 0402", Capacitance=2.2µF, Manufacturer="TDK Corporation", Manufacturer Part Number=C1005X5R0J225K050BC, Operating Temperature="-55°C ~ 85°C", Package / Case="0402 (1005 Metric)", Ratings=-, Supplier Part Number 1=445-6847-6-ND, Temperature Coefficient=X5R, Tolerance=±10%, Voltage - Rated=6.3V
C2 C4 C6 C7: library part "CAP SMD", "CAP CER 0.1UF 6.3V 10% X5R 0402", Capacitance=0.1µF, Manufacturer="TDK Corporation", Manufacturer Part Number=C1005X5R0J104K050BA, Operating Temperature="-55°C ~ 85°C", Package / Case="0402 (1005 Metric)", Ratings=-, Supplier Part Number 1=445-1266-6-ND, Temperature Coefficient=X5R, Tolerance=±10%, Voltage - Rated=6.3V
C13: library part CAP
C14 C61 C62 C63 C64 C65 C66 C67 C68 C69: library part "Cap Semi", "Capacitor (Semiconductor SIM Model)"
C15 C16 C17 C18 C19 C20 C21 C22 C23 C33 C34 C35 C36 C37 C39 C40 C42 C43 C44 C45 C59 C60 C70 C71 C72 C73 C74 C75 C76 C77 C78 C89 C90 C91 C92 C93 C94 C95 C96 C97 CC1 CC2 CC3: library part "CAP NP"
C24 C25 C46 C47 C48 C49 C50 C51: library part 4.7uFCapacitor16V10%0603, Mfr="Taiyo Yuden", MfrNum=EMK107ABJ475KA-T, PartName=4.7uF16V10%SMD0603, TIIntPartnumber=1C0103
C38: library part CAP_0, "SMD,6.3x5.4mm"
C41: library part CAP, "SMD,6.3x7.7mm"
CAN RS485: library part "Header 2"
COM1: library part "Header 9"
CORE: "FOXCONN DDR3 204P 9.2H STD", Package=None
Cp1: library part "Cap Pol3", "Polarized Capacitor (Surface Mount)"
D1: library part Zener, "DIODE SCHOTTKY 40V 120MA SOD323", Capacitance @ Vr, F="2pF @ 1V, 1MHz", Current - Average Rectified (Io)="120mA (DC)", Current - Reverse Leakage @ Vr="500nA @ 30V", Manufacturer="NXP Semiconductors", Package / Case="SC-76, SOD-323", Supplier Device Package=SOD-323, Supplier Part Number 1=568-8119-6-ND, Voltage - DC Reverse (Vr) (Max)=40V, Voltage - Forward (Vf) (Max) @ If="370mV @ 1mA"
D2 D3 D4: library part "TVS Arrays_1"
D6: library part DIODE_0
D7: library part LED
D8: library part "DIODE ZENER1_8"
Debug: library part miniusb_0
Display: library part LCD-888_0, "FPC, 45pin, 0.5mm pitch, Bottom Contact, Flip Lock"
eMOD1: library part "Header 10X2"
F1 F2: library part "Fuse 2", "Fuse 1A (1206)"
HDMI: library part HDMI_2
HeadSet: library part PJ-393
L1: library part INDUCTOR
L2 L3: library part 2.2uHInductor10%2_0.6Asmd, Mfr=TDK, MfrNum=VLCF5020T-2R2N2R6-3, PartName=2.2uH10%2.6Asmd, TIIntPartnumber=1L0025
L6: library part Inductor, "12 x 12 3A power inductor SMD"
L7: library part Inductor
LAN: library part CON10_1
onANT: "SMD Built-in Antenna 2.4GHz;2P-L9.5*W2.1*H1.0mm RainSun;AN9520 SKU: 318010004", Package=None
P1: "Header, 2-Pin"
P2 P3: library part Socket
PORT: "Header, 24-Pin, Dual row"
PWR_HDR: library part "Header 4"
PWR_IN: library part PWR2.5
PWR_SW: library part "Header 5"
Q1: library part MOSFET_N_DMG1012T_Dup1, "MOSFET, N, LOW VT, LOGIC", Manuf. Part No=DMG1012T, Manufacturer="Diodes Inc"
Q2: library part SI2301BDS-T1-E3, "P-Channel 20V 2.2A _Ta_ 700mW _Ta_ Surface Mount SOT-23-3 _TO-236_", Package="SOT-23-3 Vishay"
Q3: "P-Channel 20V 2.2A _Ta_ 700mW _Ta_ Surface Mount SOT-23-3 _TO-236_", Package="SOT-23-3 Vishay"
R1 R2 R3 R4 R5 R6 R8 R13 R14 R19 R20 R47 R48 R49 R50 R55 R65 R66 R67 R68 R69 R70 R71 R72 R73 R74 R75 R87 R88 R89 R90 R91 R92 R93 R98 R99 R100 R101 R102 R103: library part R
R7 R9 R10 R11 R12 R34 R35: library part "RES SMD", Manufacturer=Yageo, Manufacturer Part Number=RC0402FR-071K5L, Package / Case="0402 (1005 Metric)", Power (Watts)="0.063W, 1/16W", Resistance (Ohms)=1.5k, Supplier Device Package=0402, Supplier Part Number 1=311-1.50KLRDKR-ND, Temperature Coefficient=±100ppm/°C, Tolerance=±1%
R36: library part "RES SMD", "RES 27.0K OHM 1/16W 1% 0402 SMD", Manufacturer=Yageo, Manufacturer Part Number=RC0402FR-0727KL, Package / Case="0402 (1005 Metric)", Power (Watts)="0.063W, 1/16W", Resistance (Ohms)=27k, Supplier Device Package=0402, Supplier Part Number 1=311-27.0KLRDKR-ND, Temperature Coefficient=±100ppm/°C, Tolerance=±1%
R37 R38: library part "RES SMD", "RES 10K OHM 1/16W 5% 0402 SMD", Manufacturer="Rohm Semiconductor", Manufacturer Part Number=MCR01MZPJ103, Package / Case="0402 (1005 Metric)", Power (Watts)="0.063W, 1/16W", Resistance (Ohms)=10k, Supplier Part Number 1=RHM10KJDKR-ND, Temperature Coefficient=±200ppm/°C, Tolerance=±5%
R39: library part "RES SMD", Manufacturer=Yageo, Manufacturer Part Number=RC0402JR-070RL, Package / Case="0402 (1005 Metric)", Power (Watts)="0.063W, 1/16W", Resistance (Ohms)=0.0, Supplier Device Package=0402, Supplier Part Number 1=311-0.0JRDKR-ND, Temperature Coefficient=-, Tolerance=Jumper
R40 R42 R43 R51 R52 R53 R54 R60 R61 R62 R63 R76 R77 R78 R79 R80 R81 R94 R95 R96 R97 R104 R107 R109 R110 R111 R118 R119 R120 R121 R122 R123 R124 R125 R130 R131 R133 R135 R136 R145 R146 R147 R148 R149 R150 R151 R152 R153: library part 10KOhmResistor1/16W0402_Dup1, Mfr=Rohm, MfrNum=MCR01MZPJ103, PartName=10Kohm1/16W5%SMD0402, TIIntPartnumber=1R0168
R44 R45: library part RES
RN1 RN2 RN3 RN4 RN5 RN6 RN7: library part R_PAK4, "?"
RN8: library part R_PAK4
S1: "OSC; SMD; 4 Leads; Body 3.2 x 2.5  P.N: S3D24.576000D20F30T", Manufacturer=TXC, Manufacturer PN=7V
"SD CARD": library part Component_1
SIM1: library part SIMCARD_1
U1: "IC HDMI TRANSMITTER 64-HVQFN", Manufacturer="NXP Semiconductors", Manufacturer Part Number=TDA19988AHN/C1,551, Package / Case="64-VFQFN Exposed Pad", Supplier Device Package="64-HVQFN (9x9)", Supplier Part Number 1=TDA19988AHN/C1,551-ND
U2: library part Component_1, "CAN Driver"
U6: "Linear Voltage Regulator IC Output", Package="SOT-23-3 Torex"
U7: "±15kV ESD-Protected, 3.0V to 5.5V, Low-Power, up to 250kbps, True RS-232 Transceiver"
U9: library part Component_1, "+3.3V Powered, HALF DUBLEX RS-485 Driver/Receiver,8 SO PACKAGE"
U10 U12: library part GL850/2
U11: library part wifi_DJH_WF_68
USB: library part USB-HOST_0
USB_HDR: "Header, 5-Pin, Dual row"
X1 X2: library part XTAL

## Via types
v1: diameter 0.45, hole 0.2, Top Layer to Bottom Layer, tented both sides, 424 vias
v2: diameter 0.7, hole 0.5, Top Layer to Bottom Layer, tented both sides, 146 vias
v3: diameter 0.45, hole 0.25, Top Layer to Bottom Layer, tented both sides, 55 vias
v4: diameter 0.5, hole 0.3, Top Layer to Bottom Layer, tented both sides, 17 vias
v5: diameter 0.7, hole 0.4, Top Layer to Bottom Layer, tented both sides, 13 vias
v6: diameter 0.66, hole 0.33, Top Layer to Bottom Layer, tented both sides, 4 vias
v7: diameter 0.75, hole 0.5, Top Layer to Bottom Layer, tented both sides, 1 vias
v8: diameter 0.5, hole 0.2, Top Layer to Bottom Layer, tented both sides, 1 vias
v9: diameter 0.45, hole 0.3, Top Layer to Bottom Layer, tented both sides, 1 vias

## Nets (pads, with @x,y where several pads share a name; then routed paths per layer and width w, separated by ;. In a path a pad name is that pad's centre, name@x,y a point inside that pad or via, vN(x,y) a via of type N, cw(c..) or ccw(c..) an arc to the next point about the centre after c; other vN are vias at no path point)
1D1_N: R110.2 R146.1 U12.5 | length 8.8
  Top Layer w0.13: U12.5@767.627,199.29 768.5,199.29 768.6,199.39 771.942,199.39 773.176,198.157 773.71,198.157 R110.2@774.334,197.532 R146.1@774.334,196.212
1D1_P: R111.2 R145.1 U12.6 | length 8.8
  Top Layer w0.13: U12.6@767.677,199.74 768.51,199.74 768.6,199.65 772.05,199.65 773.283,198.417 773.71,198.417 R111.2@774.334,199.041 R145.1@774.334,200.403
1D2_N: R53.2 R121.1 U12.9 | length 68.6
  Top Layer w0.13: U12.9@767.627,201.29 768.56,201.29 768.656,201.386 769.4,201.386 769.49,201.295 v1(769.49,201.225)
  Layer 1 w0.13: v1(743.58,193.91) 743.74,194.07 751.24,194.07 756.93,199.76 766.845,199.76 768.47,201.386 769.33,201.386 v1(769.49,201.225)
  Layer 2 w0.13: v1(732.45,203.23) 732.45,203.31 732.53,203.39 735.14,203.39 738.39,200.14 738.39,199.8 v1(738.23,199.64)
  Bottom Layer w0.13: R121.1@723.63,219.073 R53.2@725.046,219.073 725.624,218.495 725.624,216.168 727.57,214.222 727.57,207.412 731.592,203.39 732.29,203.39 v1(732.45,203.23) ; v1(738.23,199.64) 738.26,199.64 738.39,199.51 738.39,197.592 741.912,194.07 743.42,194.07 v1(743.58,193.91)
1D2_P: R54.2 R120.1 U12.10 | length 68.2
  Top Layer w0.13: U12.10@767.677,201.74 768.57,201.74 768.665,201.645 769.4,201.645 769.49,201.736 v1(769.49,201.805)
  Top Layer w0.2: U12.10@767.627,201.79 U12.10@767.677,201.74
  Layer 1 w0.13: v1(743.58,194.49) 743.74,194.33 751.132,194.33 756.822,200.02 766.737,200.02 768.362,201.645 769.33,201.645 v1(769.49,201.805)
  Layer 2 w0.13: v1(732.45,203.81) 732.45,203.73 732.53,203.65 735.248,203.65 738.65,200.248 738.65,199.8 v1(738.81,199.64)
  Bottom Layer w0.13: R120.1@727.878,219.073 R54.2@726.462,219.073 725.884,218.495 725.884,216.276 727.83,214.33 727.83,207.52 731.7,203.65 732.29,203.65 v1(732.45,203.81) ; v1(738.81,199.64) 738.78,199.64 738.65,199.51 738.65,197.7 742.02,194.33 743.42,194.33 v1(743.58,194.49)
